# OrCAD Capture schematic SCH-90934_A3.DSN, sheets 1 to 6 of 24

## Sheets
1 C-21 BOOT MODE: size A4; title: IMX91LP4QSB-09; rev: A3; company: NXP Semiconductor; note: SCH-90934  PDF: SPF-90934; note: NO. 192 Liangjing Rd. Pudong New Area, ShangHai
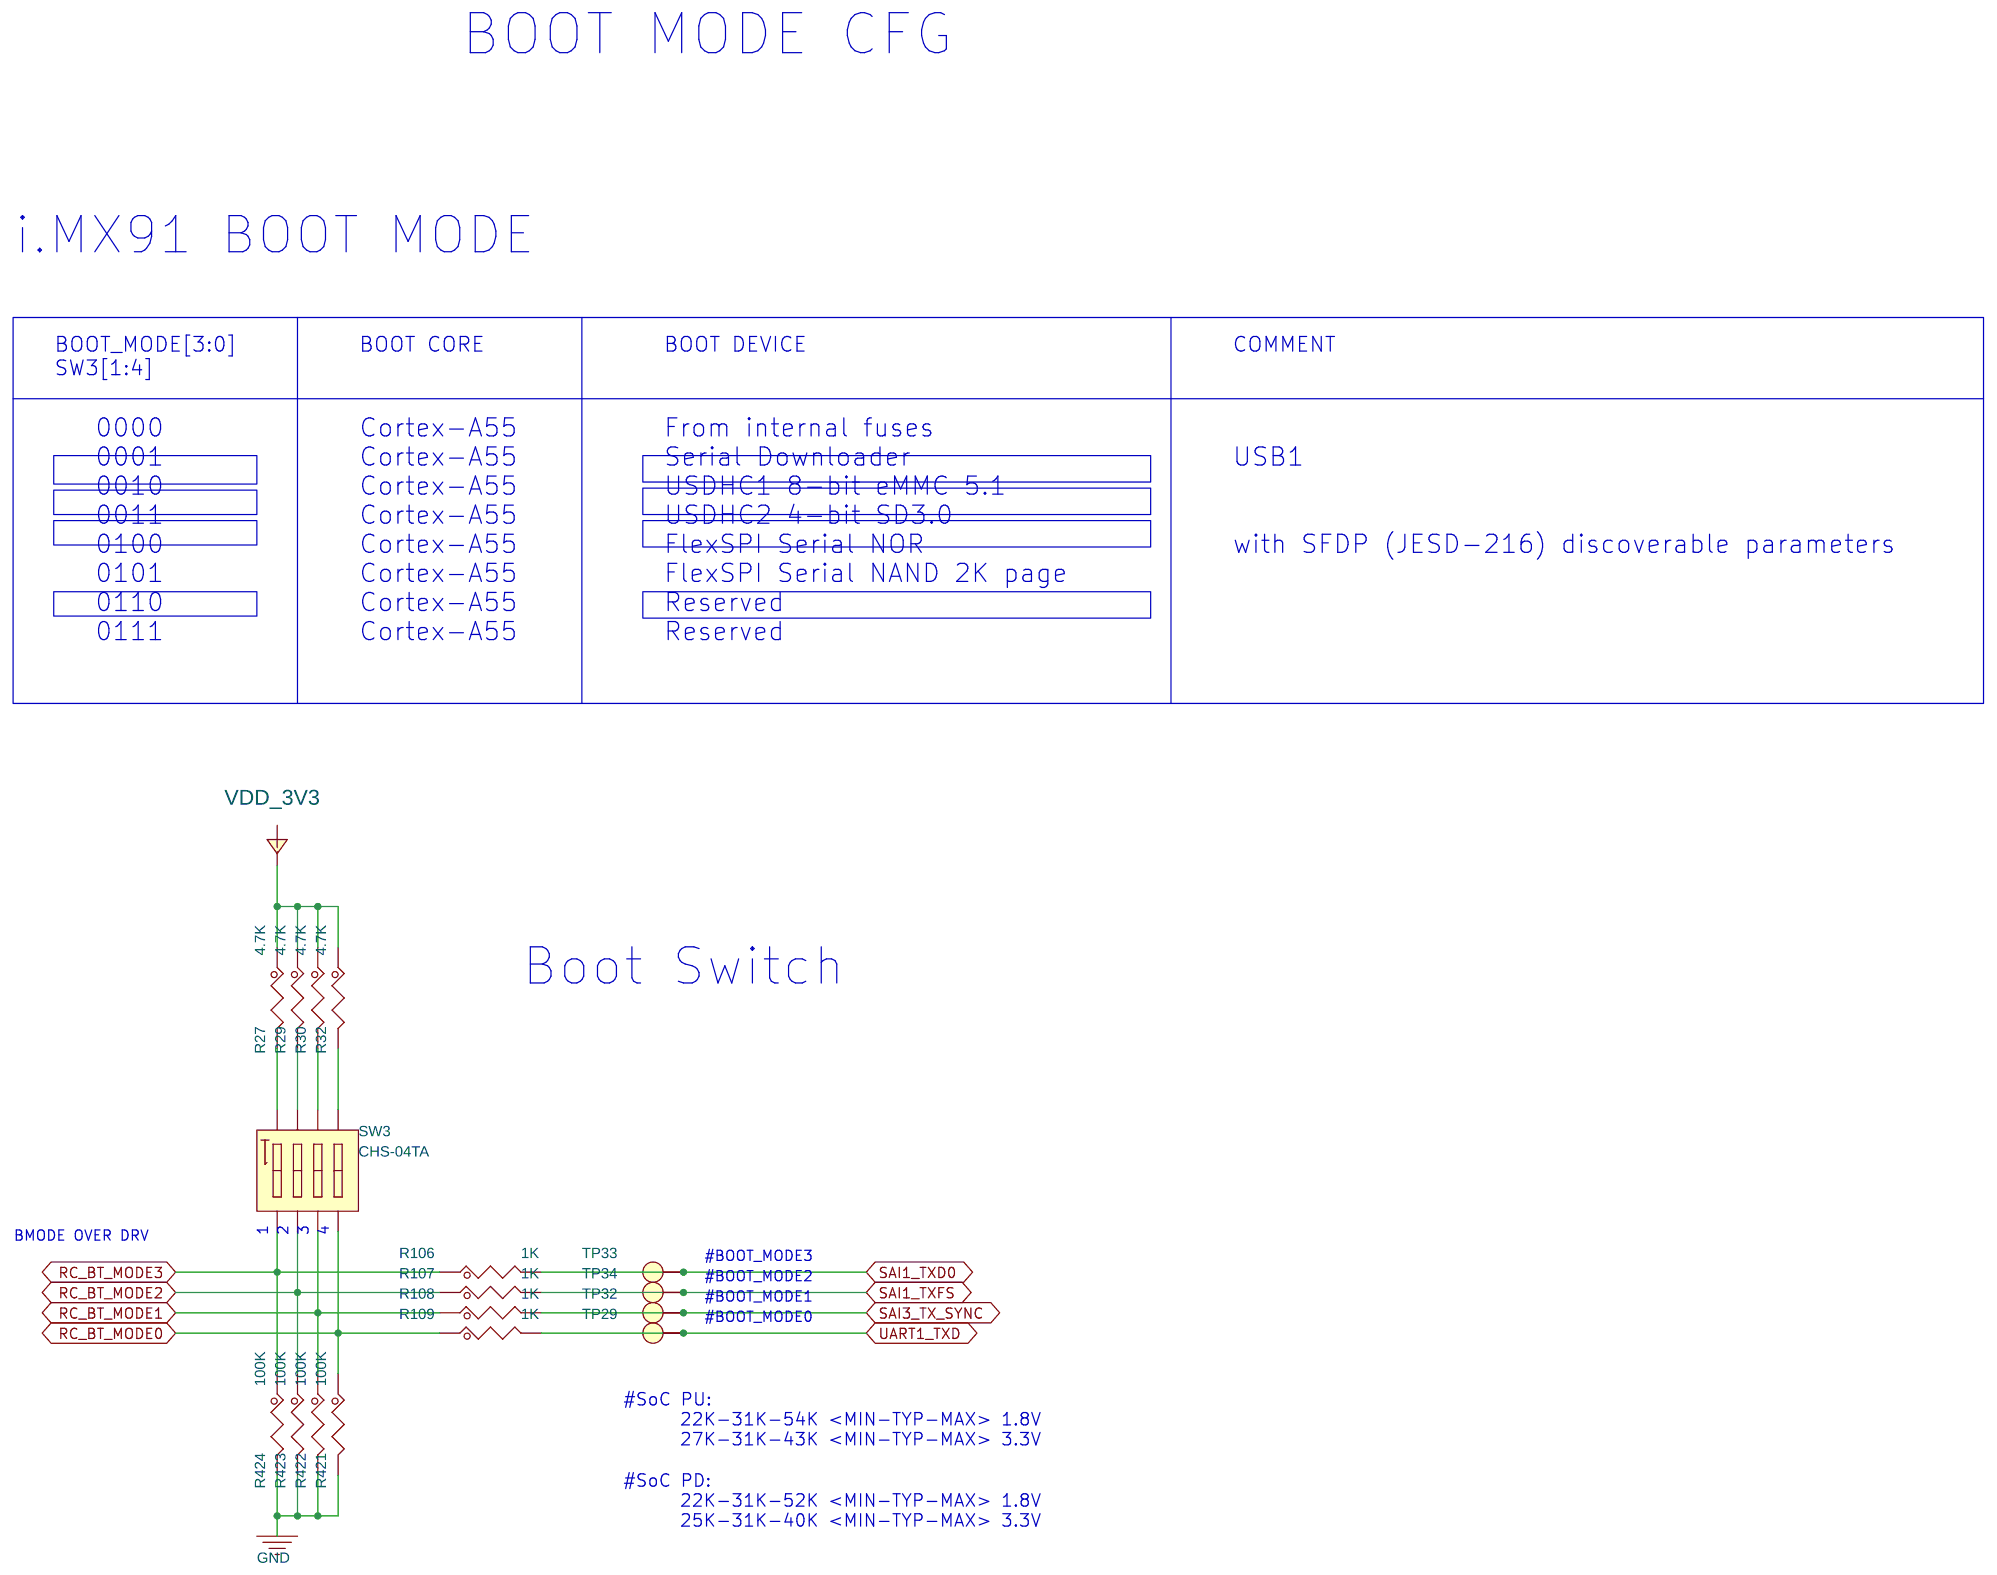
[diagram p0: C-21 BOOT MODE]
2 C-11 PWR MEAS: size A2; title: MCIMX91-SOM
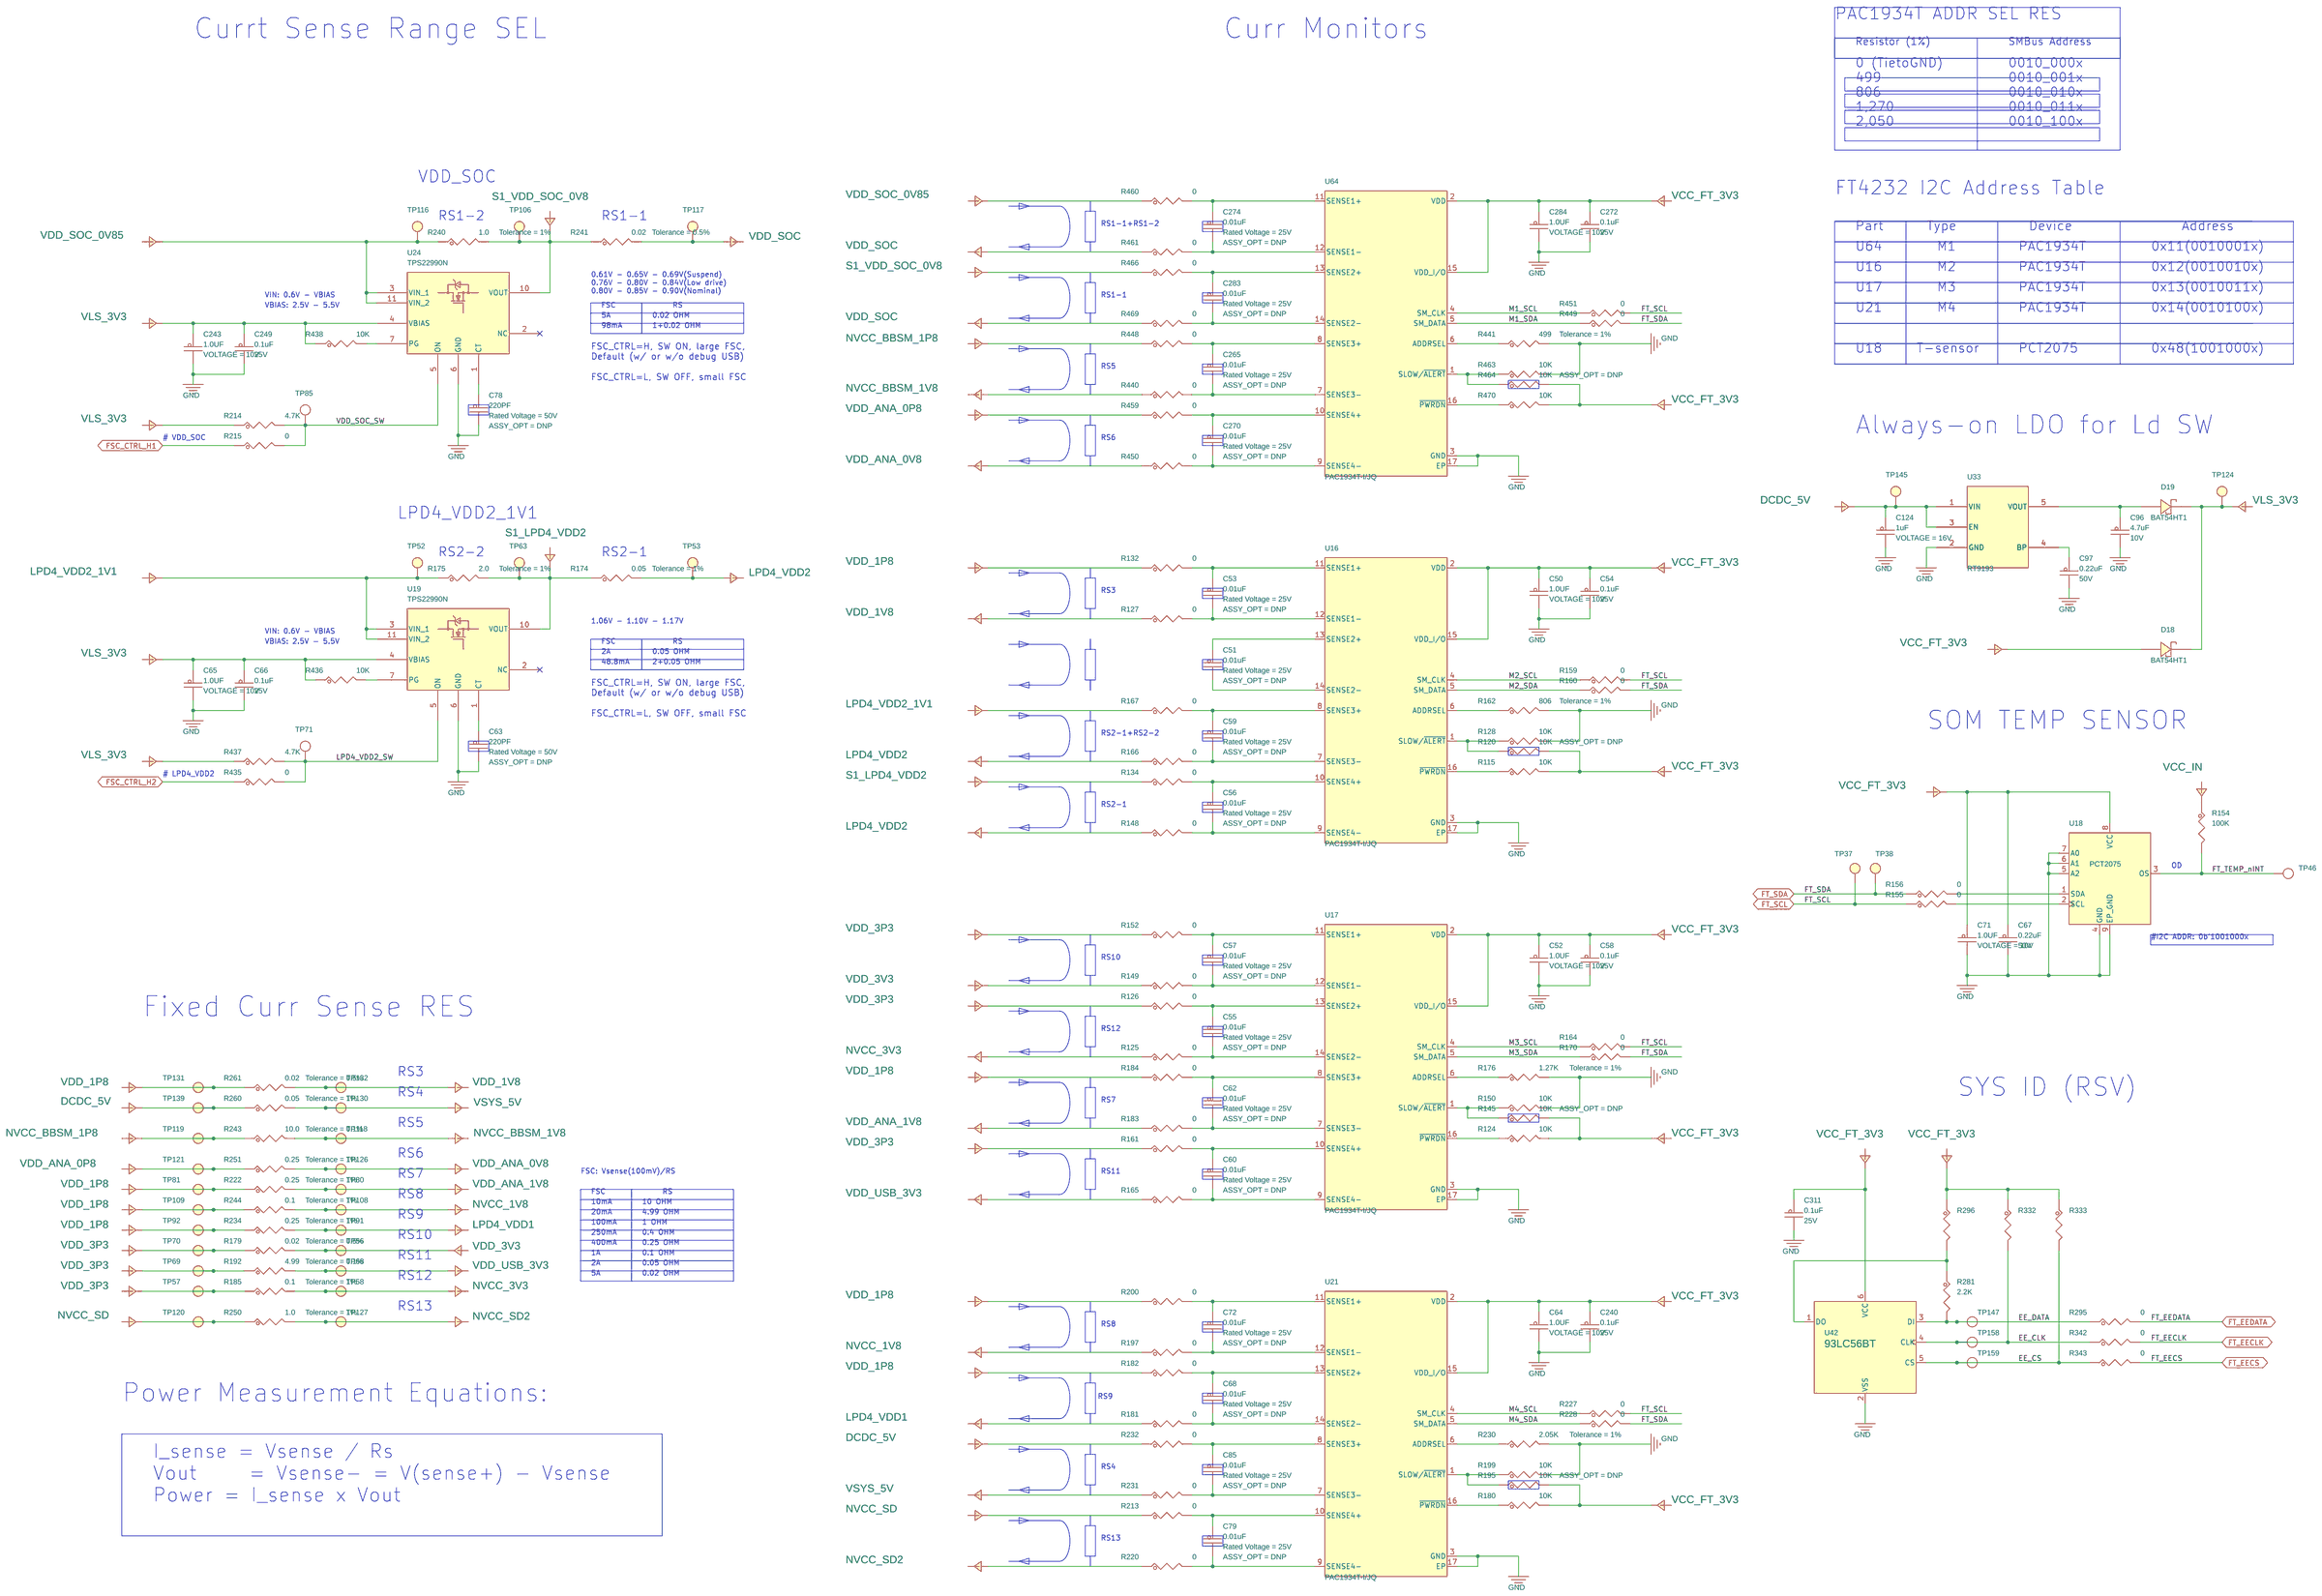
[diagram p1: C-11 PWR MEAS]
3 C-07 CPU MISC: size A3
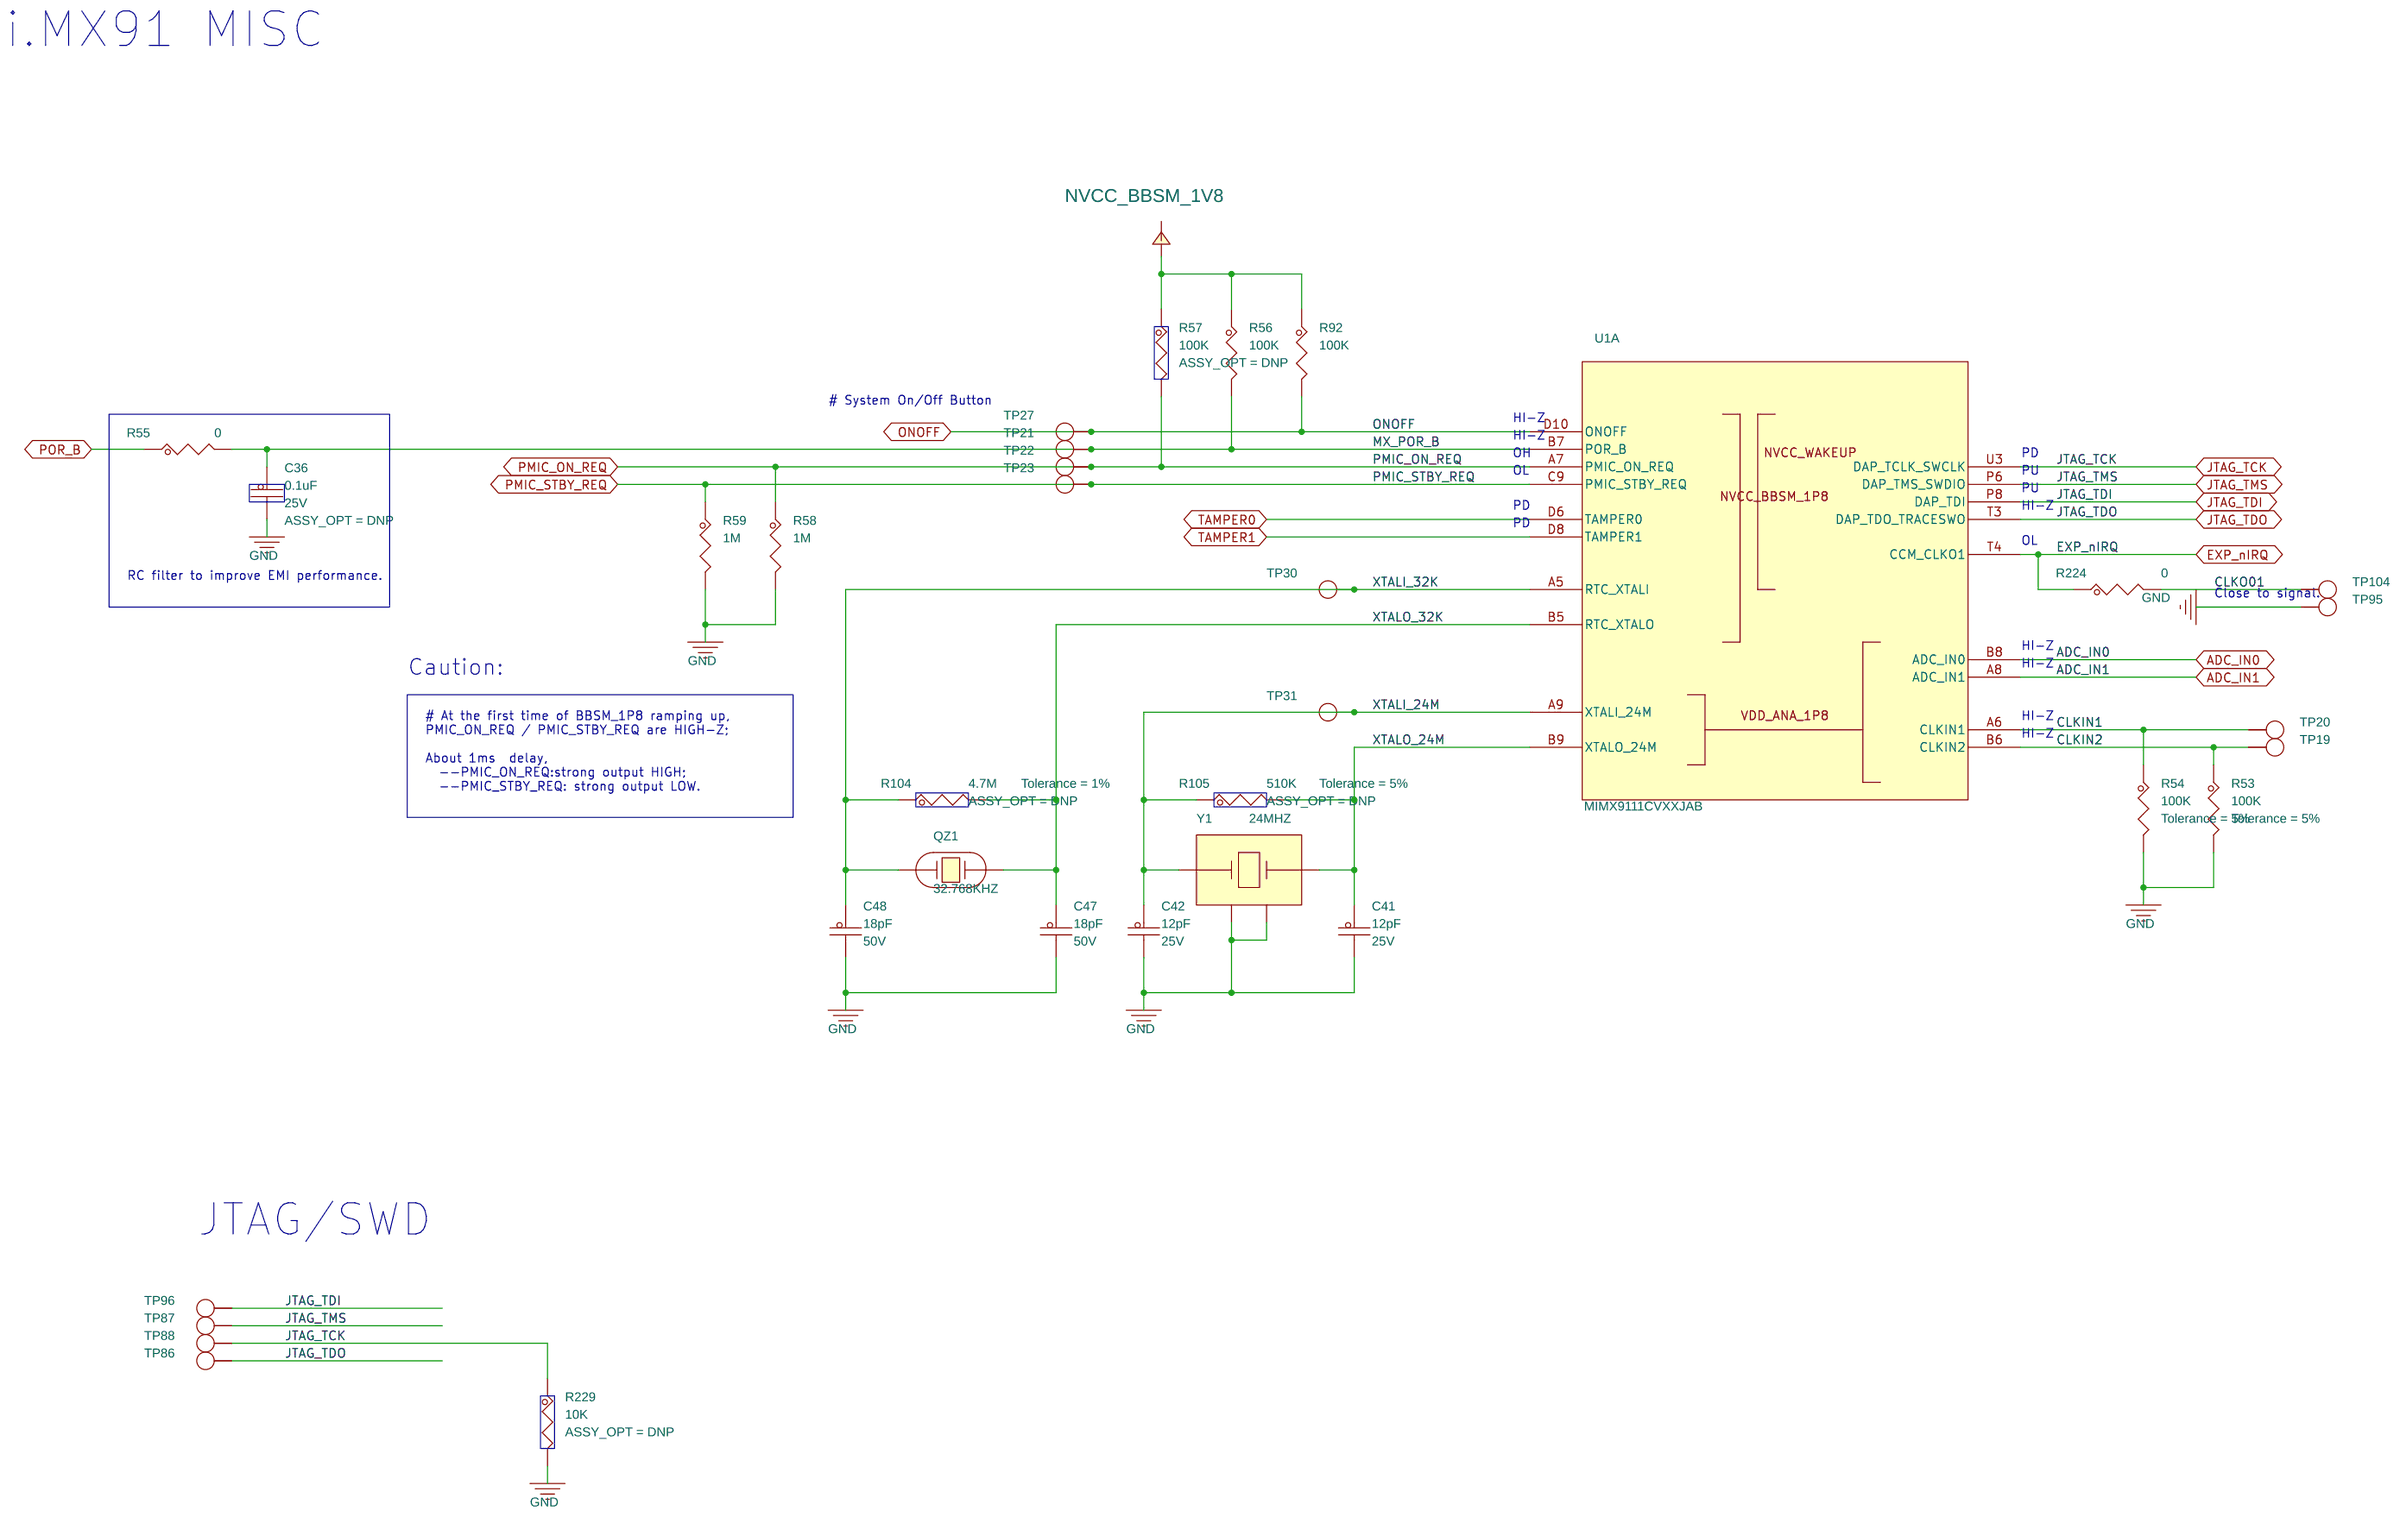
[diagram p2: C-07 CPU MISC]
4 X-24 IOMUX
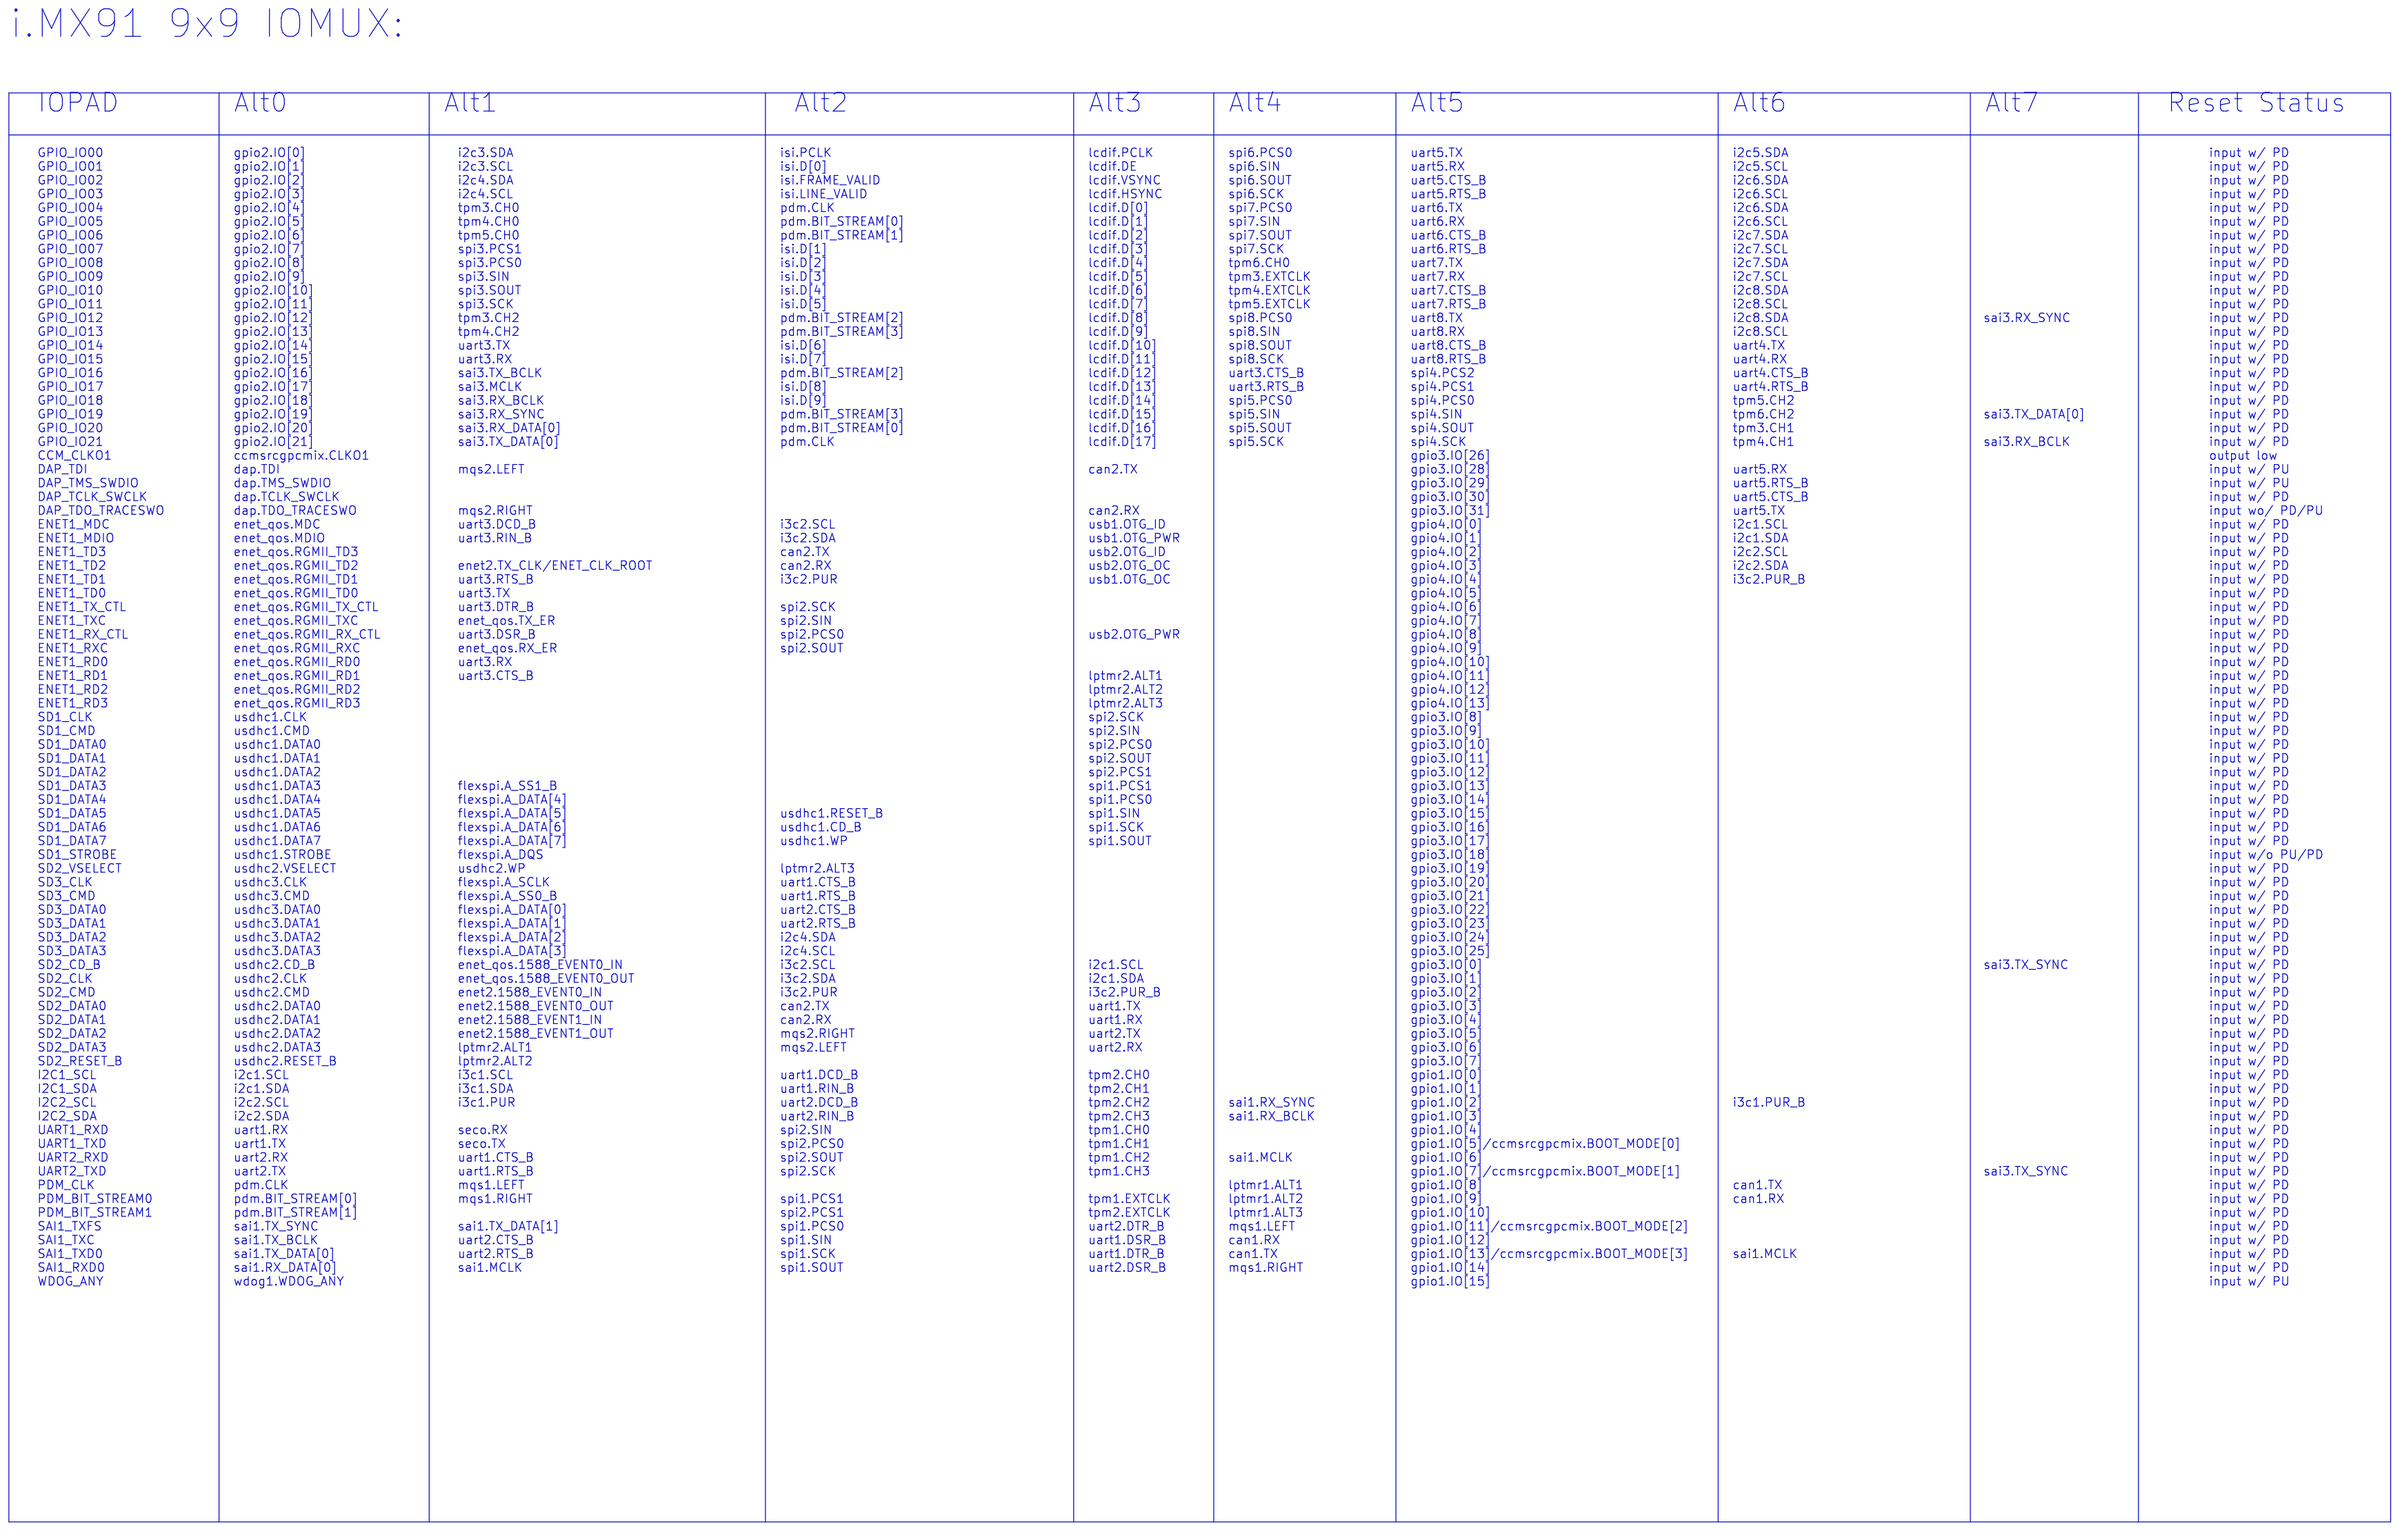
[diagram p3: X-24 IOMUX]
5 X-23 I2C TABLE
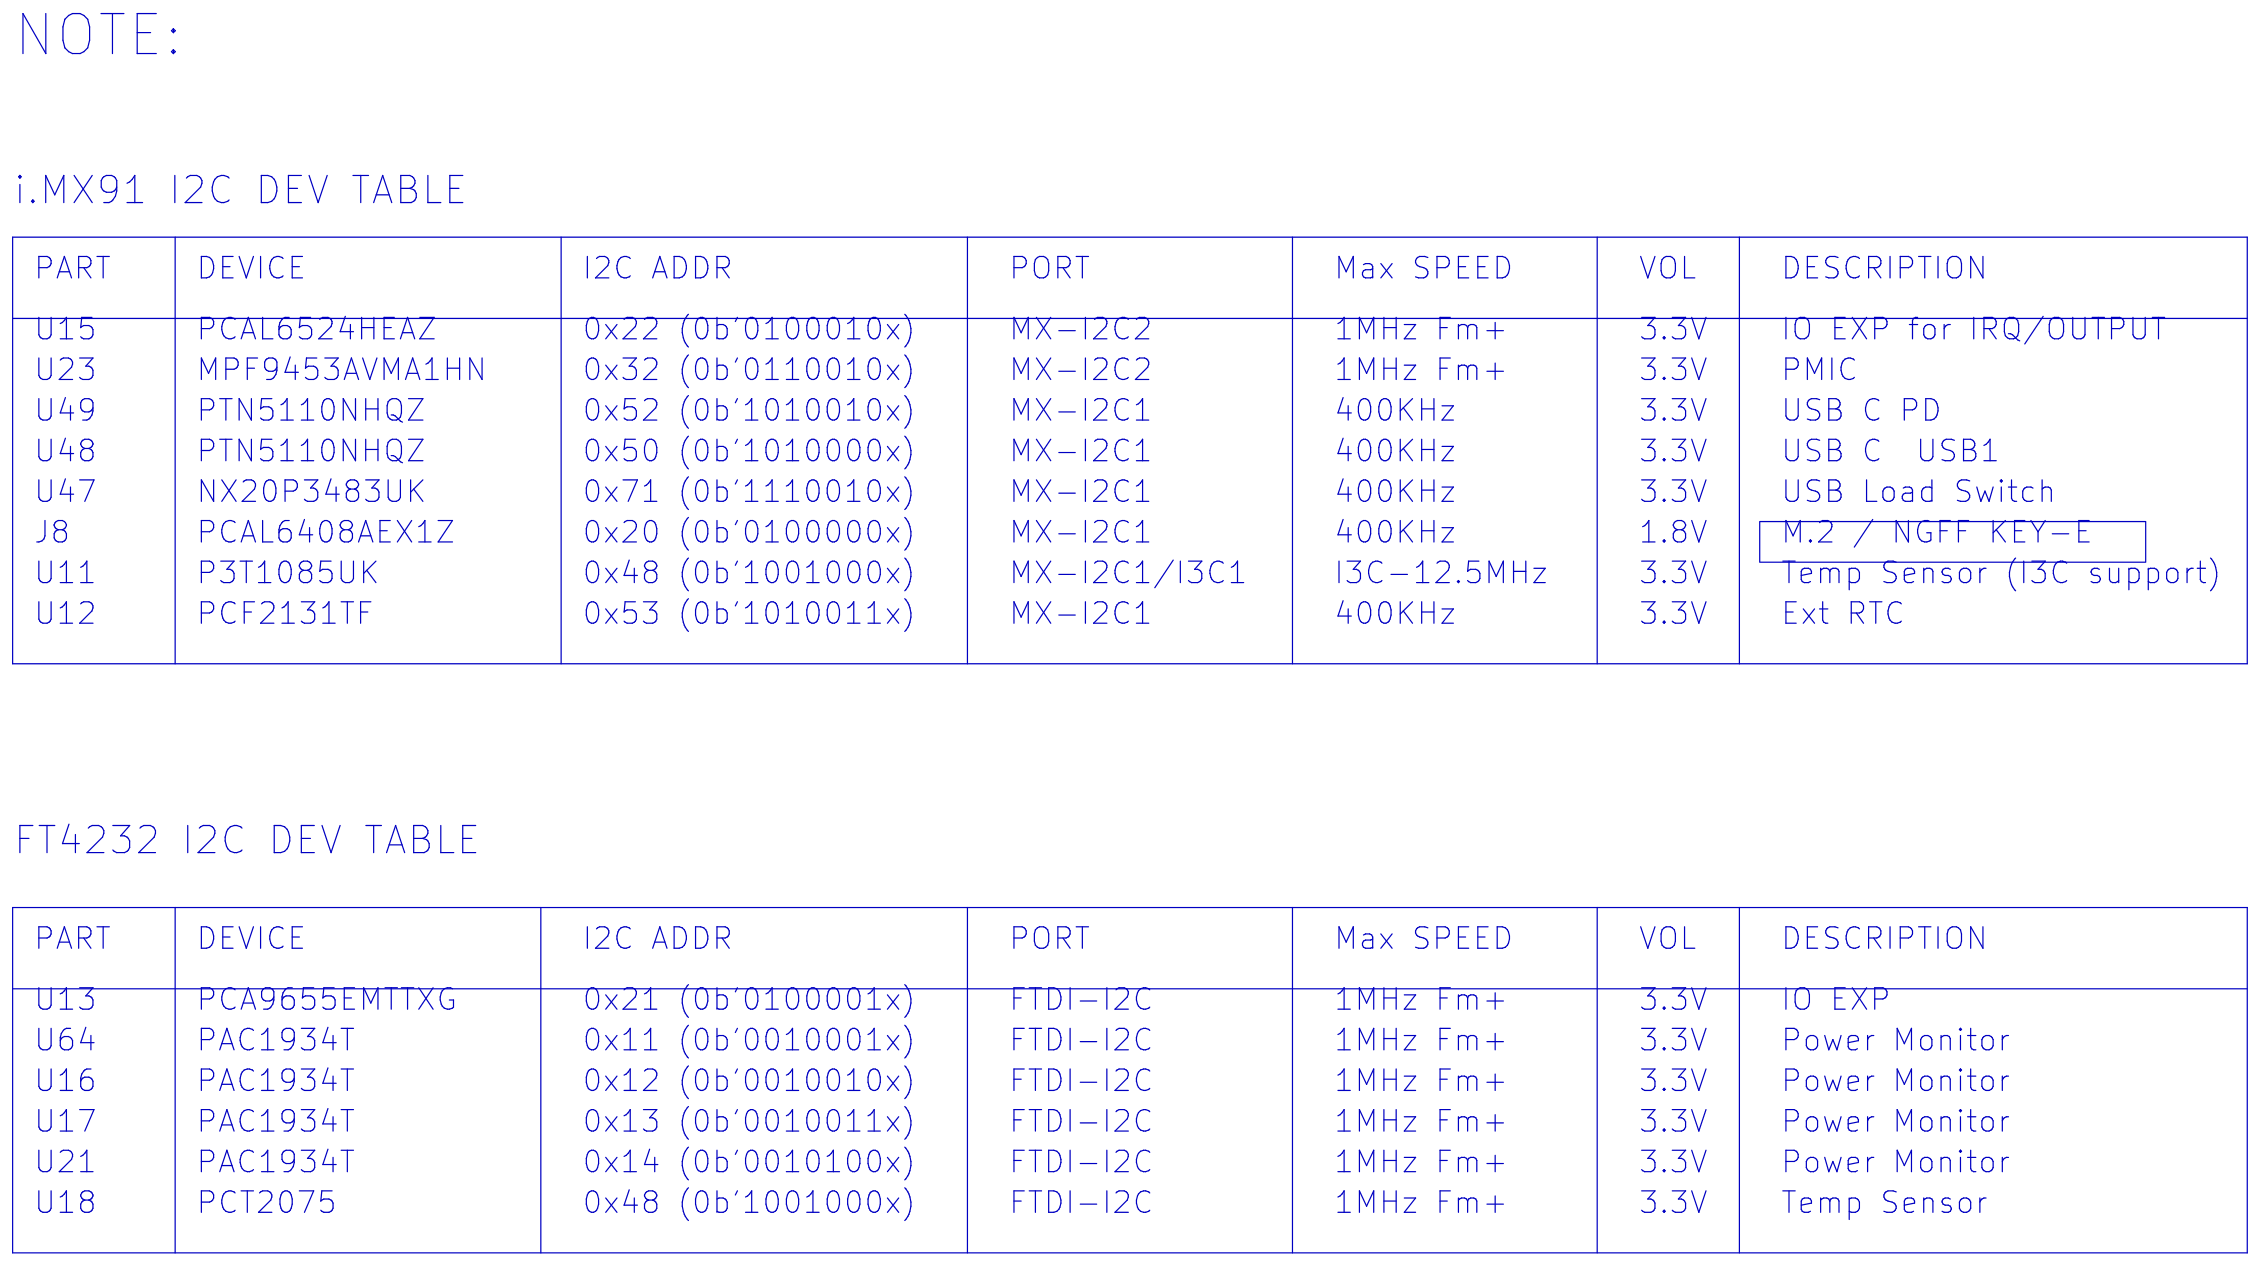
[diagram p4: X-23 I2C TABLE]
6 X-22 PWR MEAS Diagram
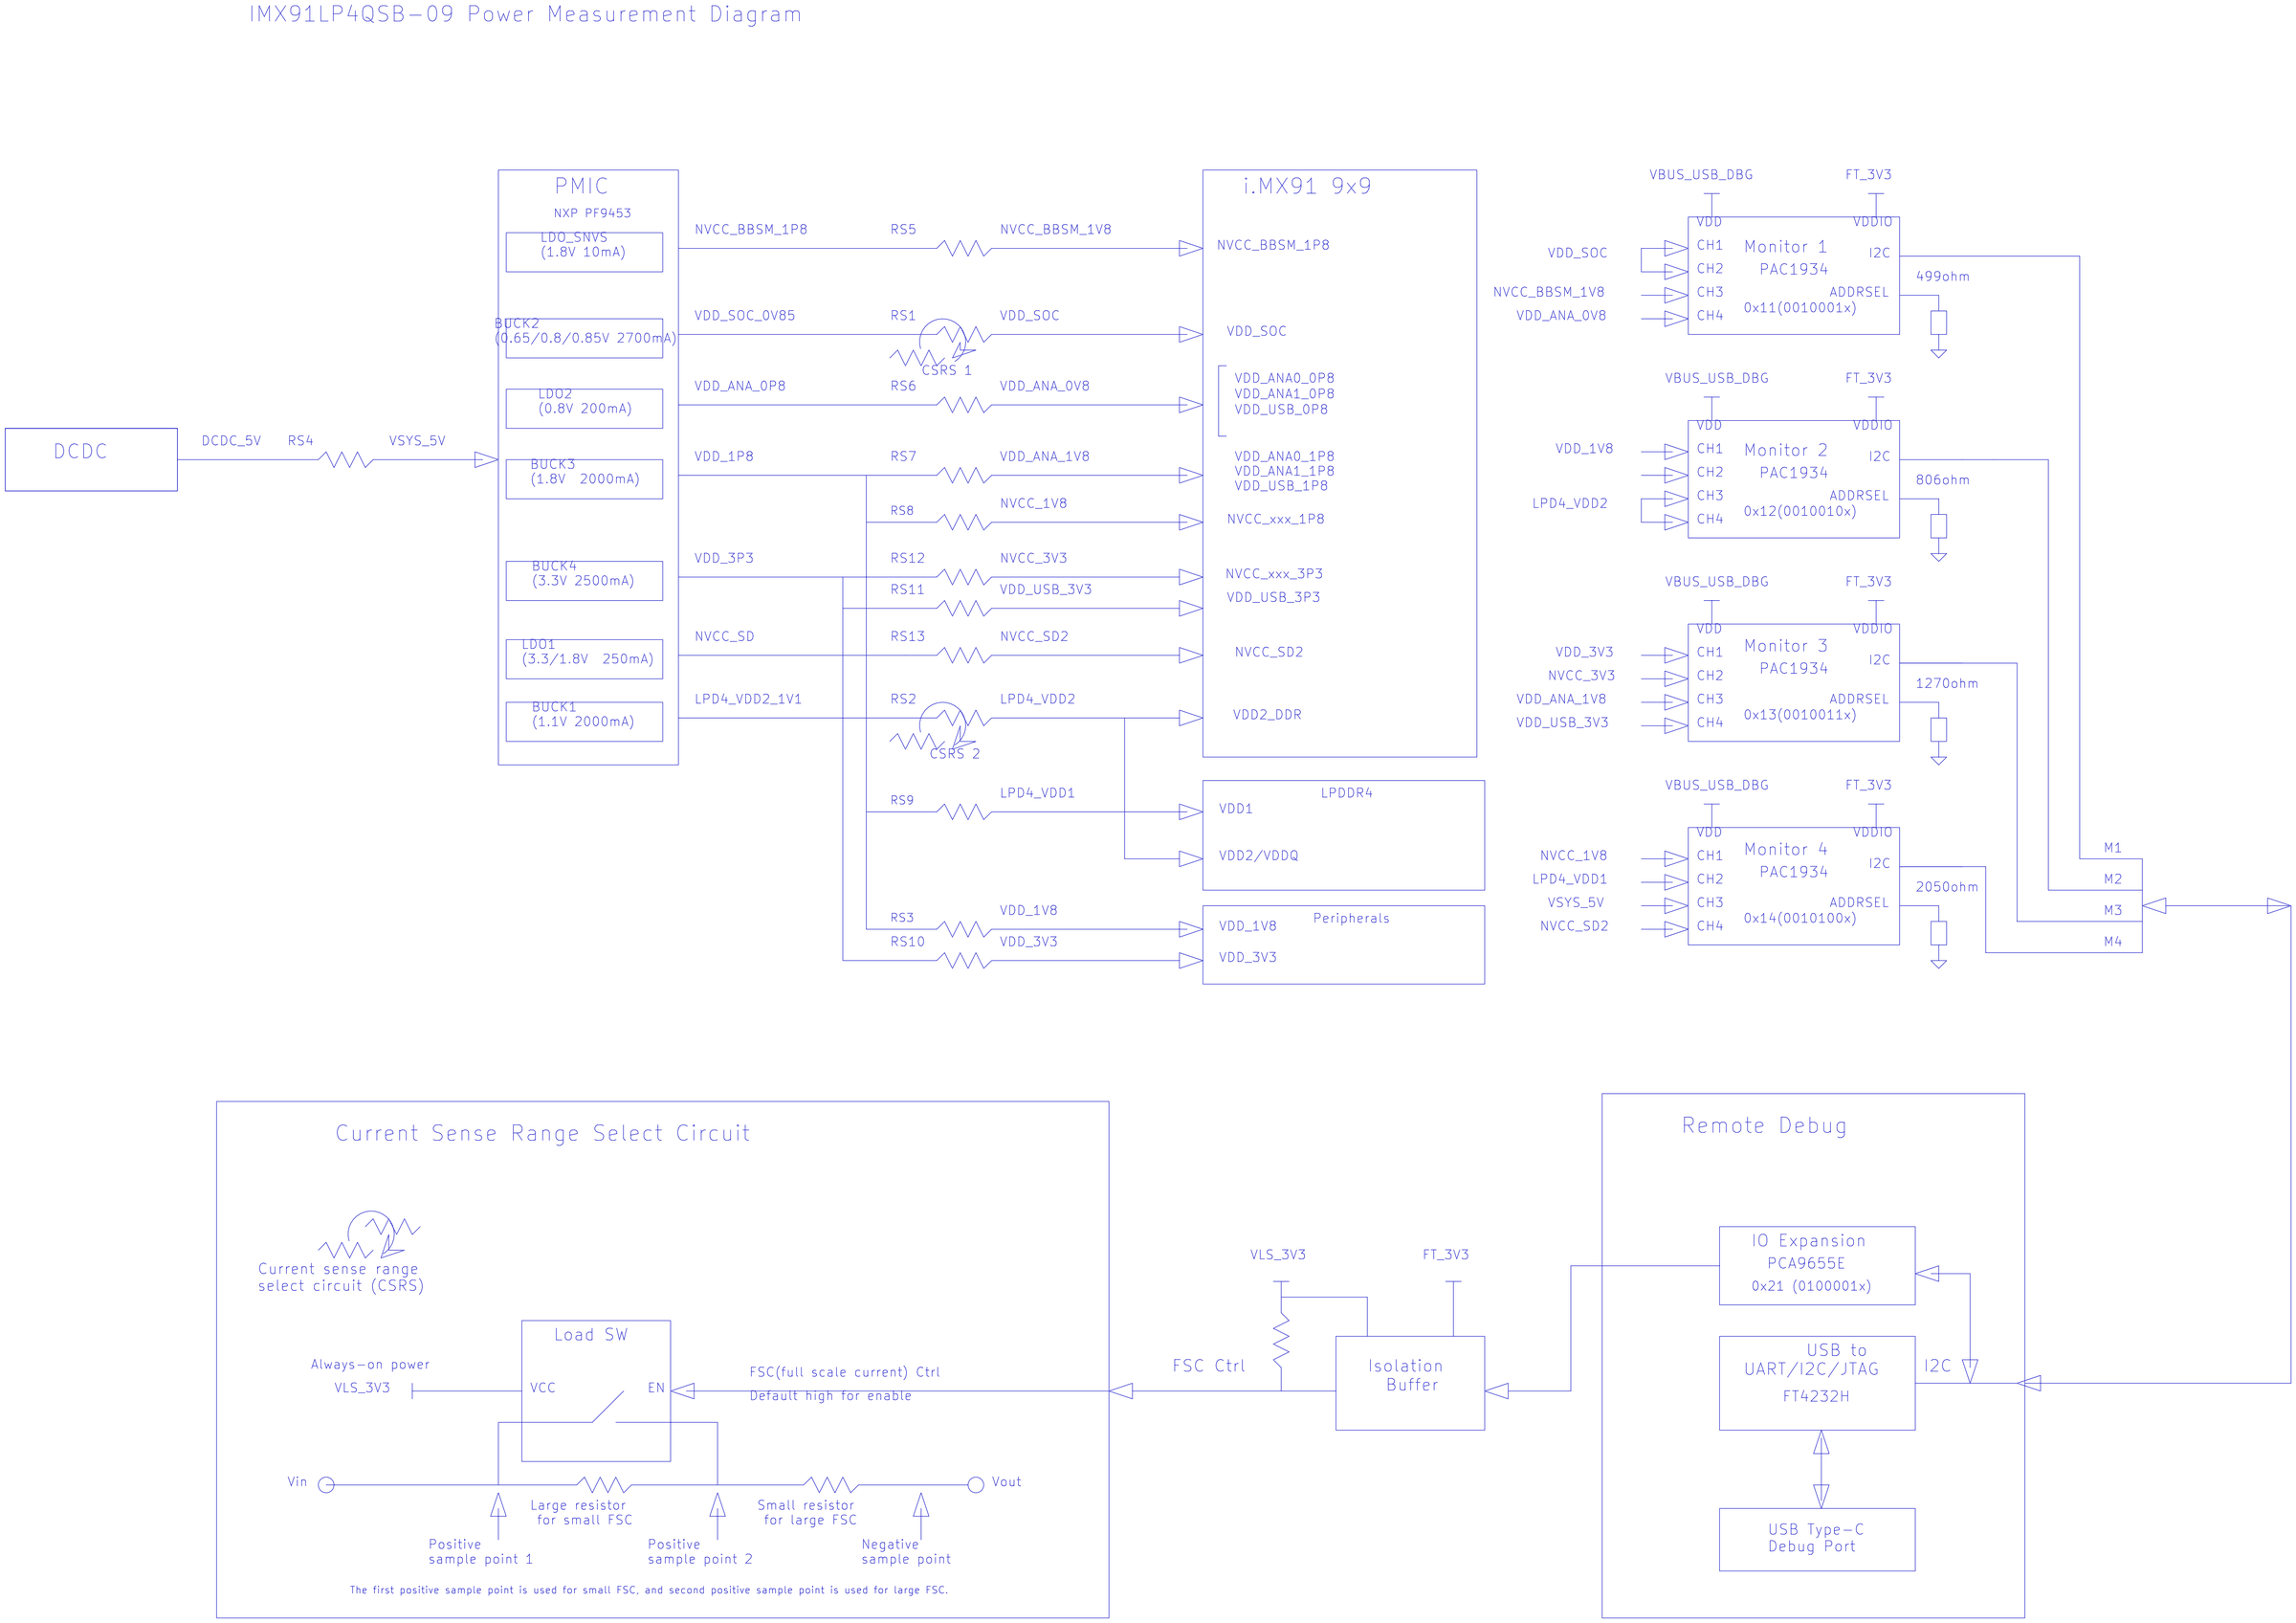
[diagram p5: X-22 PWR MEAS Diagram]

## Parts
sheet C-07 CPU MISC
C36  0.1uF  [CC0402_25]
C41  12pF  [0201_CC]
C42  12pF  [0201_CC]
C47  18pF  [0201_CC]
C48  18pF  [0201_CC]
QZ1  32.768KHZ  [XTAL2-3P2X1P5-SM]
R53  100K  [0402_CC]
R54  100K  [0402_CC]
R55  0  [0201_CC]
R56  100K  [0402_CC]
R57  100K  [0402_CC]
R58  1M  [0201_CC]
R59  1M  [0201_CC]
R92  100K  [0402_CC]
R104  4.7M  [RC0402_25]
R105  510K  [0402_CC]
R224  0  [0402_CC]
R229  10K  [0402_CC]
TP19  TPAD_020  [tpad_020]
TP20  TPAD_020  [tpad_020]
TP21  TPAD_020  [tpad_020]
TP22  TPAD_020  [tpad_020]
TP23  TPAD_020  [tpad_020]
TP27  TPAD_020  [tpad_020]
TP30  TPAD_015  [TPAD_015]
TP31  TPAD_015  [TPAD_015]
TP86  TPAD_020  [tpad_020]
TP87  TPAD_020  [tpad_020]
TP88  TPAD_020  [tpad_020]
TP95  TPAD_020  [tpad_020]
TP96  TPAD_020  [tpad_020]
TP104  TPAD_020  [tpad_020]
U1  MIMX9111CVXXJAB  [pbga208_0p5_9x9mm_sm]  (sections A,B,C,D,E,F)
Y1  24MHZ  [xtlosc4_3p2x2p5mm_sm]
sheet C-11 PWR MEAS
C50  1.0UF  [CC0402_25]
C51  0.01uF  [CC0402_25]
C52  1.0UF  [CC0402_25]
C53  0.01uF  [CC0402_25]
C54  0.1uF  [CC0402_25]
C55  0.01uF  [CC0402_25]
C56  0.01uF  [CC0402_25]
C57  0.01uF  [CC0402_25]
C58  0.1uF  [CC0402_25]
C59  0.01uF  [CC0402_25]
C60  0.01uF  [CC0402_25]
C62  0.01uF  [CC0402_25]
C63  220PF  [CC0402_25]
C64  1.0UF  [CC0402_25]
C65  1.0UF  [CC0402_25]
C66  0.1uF  [CC0402_25]
C67  0.22uF  [CC0402_25]
C68  0.01uF  [CC0402_25]
C71  1.0UF  [CC0402_25]
C72  0.01uF  [CC0402_25]
C78  220PF  [CC0402_25]
C79  0.01uF  [CC0402_25]
C85  0.01uF  [CC0402_25]
C96  4.7uF  [cc0402_tol0p15]
C97  0.22uF  [CC0402_25]
C124  1uF  [CC0402_25]
C240  0.1uF  [CC0402_25]
C243  1.0UF  [CC0402_25]
C249  0.1uF  [CC0402_25]
C265  0.01uF  [CC0402_25]
C270  0.01uF  [CC0402_25]
C272  0.1uF  [CC0402_25]
C274  0.01uF  [CC0402_25]
C283  0.01uF  [CC0402_25]
C284  1.0UF  [CC0402_25]
C311  0.1uF  [CC0402_25]
D18  BAT54HT1  [SOD323]
D19  BAT54HT1  [SOD323]
R115  10K  [0402_CC]
R120  10K  [0402_CC]
R124  10K  [0402_CC]
R125  0  [0402_CC]
R126  0  [0402_CC]
R127  0  [0402_CC]
R128  10K  [0402_CC]
R132  0  [0402_CC]
R134  0  [0402_CC]
R145  10K  [0402_CC]
R148  0  [0402_CC]
R149  0  [0402_CC]
R150  10K  [0402_CC]
R152  0  [0402_CC]
R154  100K  [0402_CC]
R155  0  [0402_CC]
R156  0  [0402_CC]
R159  0  [0201_CC]
R160  0  [0201_CC]
R161  0  [0402_CC]
R162  806  [RC0402_25]
R164  0  [0201_CC]
R165  0  [0402_CC]
R166  0  [0402_CC]
R167  0  [0402_CC]
R170  0  [0201_CC]
R174  0.05  [RC0805_OV]
R175  2.0  [RC0603_OV]
R176  1.27K  [RC0402_25]
R179  0.02  [RC0805_OV]
R180  10K  [0402_CC]
R181  0  [0402_CC]
R182  0  [0402_CC]
R183  0  [0402_CC]
R184  0  [0402_CC]
R185  0.1  [RC0805_OV]
R192  4.99  [RC0603_OV]
R195  10K  [0402_CC]
R197  0  [0402_CC]
R199  10K  [0402_CC]
R200  0  [0402_CC]
R213  0  [0402_CC]
R214  4.7K  [0402_CC]
R215  0  [0402_CC]
R220  0  [0402_CC]
R222  0.25  [RC0805_OV]
R227  0  [0201_CC]
R228  0  [0201_CC]
R230  2.05K  [RC0402_25]
R231  0  [0402_CC]
R232  0  [0402_CC]
R234  0.25  [RC0805_OV]
R240  1.0  [RC0603_OV]
R241  0.02  [RC0805_OV]
R243  10.0  [RC0603_OV]
R244  0.1  [RC0805_OV]
R250  1.0  [RC0603_OV]
R251  0.25  [RC0805_OV]
R260  0.05  [RC0805_OV]
R261  0.02  [RC0805_OV]
R281  2.2K  [RC0402_25]
R295  0  [0402_CC]
R296  10K  [0402_CC]
R332  10K  [0402_CC]
R333  10K  [0402_CC]
R342  0  [0402_CC]
R343  0  [0402_CC]
R435  0  [0402_CC]
R436  10K  [0402_CC]
R437  4.7K  [0402_CC]
R438  10K  [0402_CC]
R440  0  [0402_CC]
R441  499  [RC0402_25]
R448  0  [0402_CC]
R449  0  [0201_CC]
R450  0  [0402_CC]
R451  0  [0201_CC]
R459  0  [0402_CC]
R460  0  [0402_CC]
R461  0  [0402_CC]
R463  10K  [0402_CC]
R464  10K  [0402_CC]
R466  0  [0402_CC]
R469  0  [0402_CC]
R470  10K  [0402_CC]
TP37  TP_35MIL  [testpoint_35mil]
TP38  TP_35MIL  [testpoint_35mil]
TP46  TPAD_020  [tpad_020]
TP52  TP_35MIL  [testpoint_35mil]
TP53  TP_35MIL  [testpoint_35mil]
TP56  TP_35MIL  [testpoint_35mil]
TP57  TP_35MIL  [testpoint_35mil]
TP58  TP_35MIL  [testpoint_35mil]
TP63  TP_35MIL  [testpoint_35mil]
TP68  TP_35MIL  [testpoint_35mil]
TP69  TP_35MIL  [testpoint_35mil]
TP70  TP_35MIL  [testpoint_35mil]
TP71  TPAD_020  [tpad_020]
TP80  TP_35MIL  [testpoint_35mil]
TP81  TP_35MIL  [testpoint_35mil]
TP85  TPAD_020  [tpad_020]
TP91  TP_35MIL  [testpoint_35mil]
TP92  TP_35MIL  [testpoint_35mil]
TP106  TP_35MIL  [testpoint_35mil]
TP108  TP_35MIL  [testpoint_35mil]
TP109  TP_35MIL  [testpoint_35mil]
TP116  TP_35MIL  [testpoint_35mil]
TP117  TP_35MIL  [testpoint_35mil]
TP118  TP_35MIL  [testpoint_35mil]
TP119  TP_35MIL  [testpoint_35mil]
TP120  TP_35MIL  [testpoint_35mil]
TP121  TP_35MIL  [testpoint_35mil]
TP124  TP_35MIL  [testpoint_35mil]
TP126  TP_35MIL  [testpoint_35mil]
TP127  TP_35MIL  [testpoint_35mil]
TP130  TP_35MIL  [testpoint_35mil]
TP131  TP_35MIL  [testpoint_35mil]
TP132  TP_35MIL  [testpoint_35mil]
TP139  TP_35MIL  [testpoint_35mil]
TP145  TP_35MIL  [testpoint_35mil]
TP147  TPAD_020  [tpad_020]
TP158  TPAD_020  [tpad_020]
TP159  TPAD_020  [tpad_020]
U16  PAC1934T-I/JQ  [qfn16_0p65_4X4_a]
U17  PAC1934T-I/JQ  [qfn16_0p65_4X4_a]
U18  PCT2075  [hwson8_0p5_3p1x2p1]
U19  TPS22990N  [wson10_0p5_2p1x3p1]
U21  PAC1934T-I/JQ  [qfn16_0p65_4X4_a]
U24  TPS22990N  [wson10_0p5_2p1x3p1]
U33  RT9193  [sot23-5]
U42  93LC56BT  [sot23-6]
U64  PAC1934T-I/JQ  [qfn16_0p65_4X4_a]
sheet C-21 BOOT MODE
R27  4.7K  [RC0402_25]
R29  4.7K  [RC0402_25]
R30  4.7K  [RC0402_25]
R32  4.7K  [RC0402_25]
R106  1K  [0402_CC]
R107  1K  [0402_CC]
R108  1K  [0402_CC]
R109  1K  [0402_CC]
R421  100K  [0402_CC]
R422  100K  [0402_CC]
R423  100K  [0402_CC]
R424  100K  [0402_CC]
SW3  CHS-04TA  [sw_chs_04_a]
TP29  TP_35MIL  [testpoint_35mil]
TP32  TP_35MIL  [testpoint_35mil]
TP33  TP_35MIL  [testpoint_35mil]
TP34  TP_35MIL  [testpoint_35mil]

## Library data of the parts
C36 = CAP_NP: CAP CER 0.1UF 25V 10% X5R 0402; AGILE_PN: 150-78633; ASSY_OPT: DNP; CAD_APPROVED: Yes; FPLIST: CC0402_25,CC0402_HD,0402_CC; HEIGHT: 0.55MM; MFG_NAME01: YAGEO AMERICA; MFG_PN01: CC0402KRX5R8BB104; Package Size: 0402; ROHS: Yes; Rated Voltage: 25V; Temp Range: -55C to +85C; Tolerance: 10%; VOLTAGE: 25V
C41 C42 = CAP_NP: CAP CER 12PF 25V 5% C0G AEC-Q200 0201; AGILE_PN: 150-79813; CAD_APPROVED: Yes; FPLIST: CC0201,CC0201_HD,0201_CC; HEIGHT: 0.33MM; MFG_NAME01: TDK; MFG_PN01: CGA1A2C0G1E120J030BA; ROHS: Yes; Rated Voltage: 25V; Temp Range: -55C to +125C; Tolerance: 5%; VOLTAGE: 25V
C47 C48 = CAP_NP: CAP CER 18pF 50V 5% C0G 0201; AGILE_PN: 150-79476; CAD_APPROVED: Yes; FPLIST: CC0201,CC0201_HD,0201_CC; HEIGHT: 0.33MM; MFG_NAME01: MURATA; MFG_PN01: GRM0335C1H180JA01D; Package Size: 0201; Package Type: &#966;180mm Paper taping; ROHS: Yes; Rated Voltage: 50V; Temp Range: -55C to +125C; Tolerance: 5%; VOLTAGE: 50V
QZ1 = XTAL: XTAL 32.768KHZ 12.5PF 20PPM 3.2X1.5MM SMT; 3D_Mechanical_Footprint_File: http://fcl.am.freescale.net/ALLEGRO/step/xtal2-3p2x1p5-sm.step; AGILE_PN: 230-77653; CAD_APPROVED: Yes; HEIGHT: 0.9; MFG_NAME01: ABRACON CORPORATION; MFG_PN01: ABS07-32.768KHZ-T; ROHS: Yes
R53 R54 R56 R92 R154 R421-R424 = RES: RES MF 100K 1/16W 5% 0402; AGILE_PN: 470-75597; CAD_APPROVED: Yes; FPLIST: RC0402_25,RC0402_HD,0402_CC; HEIGHT: 0.40 MM; MFG_NAME01: VENKEL COMPANY; MFG_PN01: CR0402-16W-104JT; ROHS: Yes; Temp Range: -55C to +155C; Tolerance: 5%; VOLTAGE: 50V
R55 R159 R160 R164 R170 R227 R228 R449 R451 = RES: RES MF ZERO OHM 1/20W -- 0201; AGILE_PN: 470-76631; CAD_APPROVED: Yes; FPLIST: RC0201,0201_CC,RC0201_X2; HEIGHT: 0.30 MM; MFG_NAME01: BOURNS; MFG_PN01: CR0201-J/-000GLF; ROHS: Yes
R57 = RES: RES MF 100K 1/16W 5% 0402; AGILE_PN: 470-75597; ASSY_OPT: DNP; CAD_APPROVED: Yes; FPLIST: RC0402_25,RC0402_HD,0402_CC; HEIGHT: 0.40 MM; MFG_NAME01: VENKEL COMPANY; MFG_PN01: CR0402-16W-104JT; ROHS: Yes; Temp Range: -55C to +155C; Tolerance: 5%; VOLTAGE: 50V
R58 R59 = RES: RES MF 1.0M 1/20W 5% AEC-Q200 0201; AGILE_PN: 470-79975; CAD_APPROVED: Yes; FPLIST: RC0201,0201_CC; HEIGHT: 0.26MM; MFG_NAME01: PANASONIC; MFG_PN01: ERJ-1GNJ105C; ROHS: Yes; Temp Range: 55°C ~ 125°C; Temp_Range: 55°C ~ 125°C; Tolerance: 5%; VOLTAGE: 25V
R104 = RES: RES MF 4.7M  1/16W 1% 0402; AGILE_PN: 470-31250; ASSY_OPT: DNP; CAD_APPROVED: Yes; FPLIST: RC0402_25,RC0402_HD,0402_CC; HEIGHT: 0.40 MM; MFG_NAME01: YAGEO AMERICA; MFG_PN01: RC0402FR-074M7L; ROHS: Yes; Temp Range: -55°C ~ 155°C; Tolerance: 1%; VOLTAGE: 50V
R105 = RES: RES MF 510K 1/16W 5% 0402; AGILE_PN: 470-76166; ASSY_OPT: DNP; CAD_APPROVED: Yes; FPLIST: RC0402_25,RC0402_HD,0402_CC; HEIGHT: 0.4 MM; MFG_NAME01: PANASONIC; MFG_PN01: ERJ-2GEJ514X; ROHS: Yes; Tolerance: 5%
R125-R127 R132 R134 R148 R149 R152 R155 R156 R161 R165-R167 R181-R184 R197 R200 R213 R215 R220 R224 R231 R232 R295 R342 R343 R435 R440 R448 R450 R459-R461 R466 R469 = RES: RES MF ZERO OHM 1/16W 5% 0402; AGILE_PN: 470-75394; CAD_APPROVED: Yes; FPLIST: RC0402_25,RC0402_HD,RC0402_X2,0402_CC; HEIGHT: 0.45; MFG_NAME01: YAGEO AMERICA; MFG_PN01: RC0402JR-070RL; ROHS: Yes; Temp Range: -55 to +155C; Tolerance: 5%; VOLTAGE: 1/16W
R120 R145 R195 R229 R464 = RES: RES MF 10K 1/16W 5% 0402; AGILE_PN: 470-75557; ASSY_OPT: DNP; CAD_APPROVED: Yes; FPLIST: RC0402_25,RC0402_HD,0402_CC; HEIGHT: 0.4 MM; MFG_NAME01: VISHAY INTERTECHNOLOGY; MFG_PN01: CRCW040210K0JNED; ROHS: Yes; Tolerance: 5%
TP19-TP23 TP27 TP46 TP71 TP85-TP88 TP95 TP96 TP104 TP147 TP158 TP159 = TESTLOOP: TEST POINT PAD 0.5MM DIA SMT, NO PART TO ORDER; AGILE_PN: 211-77484; ASSY_OPT: DNP; CAD_APPROVED: Yes; HEIGHT: 0.1MM; ROHS: Yes
TP30 TP31 = TESTLOOP: TEST POINT PAD 15MIL DIA SMT, NO PART TO ORDER; AGILE_PN: 211-76645; ASSY_OPT: DNP; CAD_APPROVED: Yes; HEIGHT: 0.1MM; MFG_NAME01: NOTACOMPONENT; MFG_PN01: NOTACOMPONENT; ROHS: Yes
U1 = MIMX9122DVXxLAA_BGA208_A: IC CPU SINGLE CORTEX A55 1.4GHz -- FCPBGA208; 3D_Mechanical_Footprint_File: http://fcl.am.freescale.net/ALLEGRO/step/pbga208_0p5_9x9mm_sm.STEP; AGILE_PN: 330-10031; CAD_APPROVED: Yes; HEIGHT: 1mm; MFG_NAME01: NXP SEMICONDUCTOR; Package Size: FCPBGA208; ROHS: NULL; Temp Range: -40  °C to +105 °C
Y1 = XTAL_13: XTAL 24MHZ 9pF -- SMT 3.2X2.5MM; AGILE_PN: 230-77392; CAD_APPROVED: Yes; HEIGHT: 0.60; MFG_NAME01: EPSON TOYOCOM CORPORATION; MFG_PN01: TSX-3225 24.0000MF15X-AC3; ROHS: Yes
C50 C52 C64 C65 C71 C243 C284 = CAP_NP: CAP CER 1.0UF 10V 10% X5R 0402; AGILE_PN: 150-75772; CAD_APPROVED: Yes; FPLIST: CC0402_25,CC0402_HD,0402_CC; HEIGHT: 0.6MM; MFG_NAME01: YAGEO AMERICA; MFG_PN01: CC0402KRX5R6BB105; Package Size: 0402; ROHS: Yes; Rated Voltage: 10V; SIGNAL_MODEL: DEFAULT_CAPACITOR_1e+06pF_2_1; TOL: 10%; Temp Range: -55C to +85C; Tolerance: 10%; VOLTAGE: 10V; voltage rating: 10V
C51 C53 C55-C57 C59 C60 C62 C68 C72 C79 C85 C265 C270 C274 C283 = CAP_NP: CAP CER 0.01uF 25V 5% X7R 0402; 3D_Mechanical_Footprint_File: http://fcl.am.freescale.net/ALLEGRO/step/cc0402_25.STEP; AGILE_PN: 150-81047; ASSY_OPT: DNP; CAD_APPROVED: Yes; FPLIST: CC0402_25,CC0402_HD,0402_CC,capc0402_l; HEIGHT: 0.55 MM; MFG_NAME01: KEMET; MFG_PN01: C0402C103J3RAC7867; Package Size: 0402 (1005 Metric); Package Type: Surface Mount, MLCC; ROHS: Yes; Rated Voltage: 25V; Temp Range: -55C to +125C; Tolerance: 5%
C54 C58 C66 C240 C249 C272 C311 = CAP_NP: CAP CER 0.1UF 25V 10% X5R 0402; AGILE_PN: 150-78633; CAD_APPROVED: Yes; FPLIST: CC0402_25,CC0402_HD,0402_CC; HEIGHT: 0.55MM; MFG_NAME01: YAGEO AMERICA; MFG_PN01: CC0402KRX5R8BB104; Package Size: 0402; ROHS: Yes; Rated Voltage: 25V; Temp Range: -55C to +85C; Tolerance: 10%; VOLTAGE: 25V
C63 C78 = CAP_NP: CAP CER 220PF 50V 5% C0G 0402; AGILE_PN: 150-30297; ASSY_OPT: DNP; CAD_APPROVED: Yes; FPLIST: CC0402_25,CC0402_HD,0402_CC,capc0402_l; HEIGHT: 0.55MM; MFG_NAME01: KEMET; MFG_PN01: C0402C221J5GAC; Package Size: 0402; ROHS: Yes; Rated Voltage: 50V; Temp Range: -55C to +125C; Tolerance: 5%
C67 C97 = CAP_NP: CAP CER 0.22uF 50V 10% X5R 0402; AGILE_PN: 150-79999; CAD_APPROVED: Yes; FPLIST: CC0402_25,CC0402_HD,0402_CC; HEIGHT: 0.55MM; MFG_NAME01: TAIYO YUDEN; MFG_PN01: UMK105BJ224KV-F; Package Size: 0402; ROHS: Yes; Rated Voltage: 50V; Temp Range: -55C to +85C; Temp_Range: -55°C to +85°C; Tolerance: 10%; VOLTAGE: 50V
C96 = CAP_NP: CAP CER 4.7uF 10V 10% X5R 0402; AGILE_PN: 150-80044; CAD_APPROVED: Yes; FPLIST: cc0402_tol0p15,cc0402_tol0p15_ov,0402_cc_nsp; HEIGHT: 0.65MM; MFG_NAME01: SAMSUNG ELECTRO MECHANICS; MFG_PN01: CL05A475KP5NRNC; ROHS: Yes; Rated Voltage: 10V; Temp Range: -55C to +85C; Tolerance: 10%; VOLTAGE: 10V
C124 = CAP_NP: CAP CER 1uF 16V 10% X5R 0402; AGILE_PN: 150-78973; CAD_APPROVED: Yes; FPLIST: CC0402_25,CC0402_HD,0402_CC; HEIGHT: 0.55 MM; MFG_NAME01: TDK; MFG_PN01: C1005X5R1C105K; ROHS: Yes; Rated Voltage: 16V; Temp Range: -55C to +85C; Tolerance: 10%; VOLTAGE: 16V; voltage rating: 16V
D18 D19 = DIODE_SCHTKY: DIODE SCH 30V 200MA -- SOD323; AGILE_PN: 480-30039; CAD_APPROVED: Yes; HEIGHT: 1.15; MFG_NAME01: ON SEMICONDUCTOR; MFG_PN01: BAT54HT1G
R115 R124 R128 R150 R180 R199 R296 R332 R333 R436 R438 R463 R470 = RES: RES MF 10K 1/16W 5% 0402; AGILE_PN: 470-75557; CAD_APPROVED: Yes; FPLIST: RC0402_25,RC0402_HD,0402_CC; HEIGHT: 0.4 MM; MFG_NAME01: VISHAY INTERTECHNOLOGY; MFG_PN01: CRCW040210K0JNED; ROHS: Yes; Tolerance: 5%
R162 = RES: RES TF 806 OHM 1% 1/10W AEC-Q200 0402; AGILE_PN: 470-81001; CAD_APPROVED: Yes; FPLIST: RC0402_25,RC0402_HD,0402_CC; HEIGHT: 0.4MM; MFG_NAME01: PANASONIC; MFG_PN01: ERJ-2RKF8060X; ROHS: Yes; Tolerance: 1%
R174 R260 = RES: RES MF 0.05OHM 1/4W 1% 0805; AGILE_PN: 470-79239; CAD_APPROVED: Yes; FPLIST: RC0805_OV,RC0805,0805_CC; HEIGHT: 0.46MM; MFG_NAME01: VISHAY INTERTECHNOLOGY; MFG_PN01: WSL0805R0500FEA18; ROHS: Yes; Tolerance: 1%
R175 = RES: RES MF 2.0 OHM 1/8W 1% AEC-Q200 0603; AGILE_PN: 470-81851; CAD_APPROVED: Yes; FPLIST: RC0603_OV,RC0603,0603_CC; HEIGHT: 0.55MM; MFG_NAME01: KOA SPEER; MFG_PN01: RK73H1JTTD2R00F; ROHS: Yes; Temp Range: -55°C to +155°C; Tolerance: 1%
R176 = RES: RES MF 1.27K  1/10W 1% AEC-Q200 0402; AGILE_PN: 470-30846; CAD_APPROVED: Yes; FPLIST: RC0402_25,RC0402_HD,0402_CC; HEIGHT: 0.40 MM; MFG_NAME01: KOA SPEER; MFG_PN01: RK73H1ETTP1271F; ROHS: Yes; Temp Range: -55°C to +155°C; Tolerance: 1%; VOLTAGE: 50V
R179 R241 R261 = RES: RES MF 0.02OHM 1/4W 0.5% 0805; AGILE_PN: 470-79241; CAD_APPROVED: Yes; FPLIST: RC0805_OV,RC0805,0805_CC; HEIGHT: 0.46MM; MFG_NAME01: VISHAY INTERTECHNOLOGY; MFG_PN01: WSL0805R0200DEA18; ROHS: Yes; Tolerance: 0.5%
R185 R244 = RES: RES MF 0.1 OHM 1/4W 1% AEC-Q200 0805; AGILE_PN: 470-82403; CAD_APPROVED: Yes; FPLIST: RC0805_OV,RC0805,0805_CC; HEIGHT: 0.584MM; MFG_NAME01: VISHAY INTERTECHNOLOGY; MFG_PN01: WSL0805R1000FEA18; ROHS: Yes; Temp Range: -65° C to +170° C; Tolerance: 1%
R192 = RES: RES MF 4.99 OHM 0.1% 1/16W 0603; AGILE_PN: 470-82515; CAD_APPROVED: Yes; FPLIST: RC0603_OV,RC0603,0603_CC; HEIGHT: 0.55MM; MFG_NAME01: TE CONNECTIVITY LTD; MFG_PN01: CPF0603B4R99E1; Package Size: 0603 (1608 Metric); ROHS: Yes; Temp Range: -55°C ~ 155°C; Tolerance: 0.1%
R214 R437 = RES: RES MF 4.7K 1/10W 5% AEC-Q200 0402; AGILE_PN: 470-82064; CAD_APPROVED: Yes; FPLIST: RC0402_25,RC0402_HD,0402_CC,RC0402_X2; HEIGHT: 0.41mm; MFG_NAME01: KOA SPEER; MFG_PN01: RK73B1ETTP472J; ROHS: Yes; Temp Range: -55C to +155C; Tolerance: 5%; VOLTAGE: 50V
R222 R234 R251 = RES: RES 0.25 OHM 1% 1/8W 0805; AGILE_PN: 470-82521; CAD_APPROVED: Yes; FPLIST: RC0805_OV,RC0805,0805_CC; HEIGHT: 0.6MM; MFG_NAME01: Yageo; MFG_PN01: RL0805FR-070R25L; Package Size: 0805 (2012 Metric); ROHS: Yes; Temp Range: -55 °C to +125 °C; Tolerance: 1%
R230 = RES: RES MF 2.05K  1/10W 1% AEC-Q200 0402; AGILE_PN: 470-30868; CAD_APPROVED: Yes; FPLIST: RC0402_25,RC0402_HD,0402_CC; HEIGHT: 0.40 MM; MFG_NAME01: KOA SPEER; MFG_PN01: RK73H1ETTP2051F; ROHS: Yes; Temp Range: -55C to +155C; Tolerance: 1%; VOLTAGE: 50V
R240 R250 = RES: RES MF 1.00 OHM 1/10W 1% 0603; AGILE_PN: 470-30469; CAD_APPROVED: Yes; FPLIST: RC0603_OV,RC0603,0603_CC; HEIGHT: 0.55 MM; MFG_NAME01: YAGEO AMERICA; MFG_PN01: RC0603FR-071RL; ROHS: Yes; Tolerance: 1%
R243 = RES: RES MF 10 OHM 1/16W 0.1% 0603; AGILE_PN: 470-82209; CAD_APPROVED: Yes; FPLIST: RC0603_OV,RC0603,0603_CC; HEIGHT: 0.55MM; MFG_NAME01: TE CONNECTIVITY LTD; MFG_PN01: CPF0603B10RE1; ROHS: Yes; Temp Range: -55C to +155C; Tolerance: 0.1%
R281 = RES: RES MF 2.2K 1/16W 5% 0402; AGILE_PN: 470-75636; CAD_APPROVED: Yes; FPLIST: RC0402_25,RC0402_HD,0402_CC; HEIGHT: 0.4 MM; MFG_NAME01: BOURNS; MFG_PN01: CR0402-JW-222GLF; ROHS: Yes; Tolerance: 5%
R441 = RES: RES MF 499 OHM 1/16W 1% 0402; AGILE_PN: 470-30807; CAD_APPROVED: Yes; FPLIST: RC0402_25,RC0402_HD,0402_CC; HEIGHT: 0.40 MM; MFG_NAME01: ROHM; MFG_PN01: MCR01MZPF4990; ROHS: Yes; Tolerance: 1%
TP29 TP32-TP34 TP37 TP38 TP52 TP53 TP56-TP58 TP63 TP68-TP70 TP80 TP81 TP91 TP92 TP106 TP108 TP109 TP116-TP121 TP124 TP126 TP127 TP130-TP132 TP139 TP145 = T_POINT_R: TEST POINT PAD .035 SMT, no part to order; AGILE_PN: 510-75618; ASSY_OPT: DNP; CAD_APPROVED: Yes; HEIGHT: 0.1MM; ROHS: Yes
U16 U17 U21 U64 = PAC1934_UQFN16_A: IC MULTI CHANNEL POWER/ENERGY MONITOR  2.7-5.5V UQFN16; 3D_Mechanical_Footprint_File: http://fcl.am.freescale.net/ALLEGRO/step/qfn16_0p65_4X4_a.step; AGILE_PN: 312-82072; CAD_APPROVED: Yes; HEIGHT: 0.55; MFG_NAME01: MICROCHIP TECHNOLOGY INC; ROHS: Yes; Temp Range: -40C to 85C; VOLTAGE: 2.7-5.5V
U18 = PCT2075__SON8_EP: IC I2C DIGITAL TEMP SENSOR AND THERMAL WDG 2.7-5.5V HWSON8; 3D_Mechanical_Footprint_File: http://fcl.am.freescale.net/ALLEGRO/step/hwson8_0p5_3p1x2p1.STEP; AGILE_PN: 312-81267; CAD_APPROVED: Yes; HEIGHT: 0.8; MFG_NAME01: NXP SEMICONDUCTORS; MFG_PN01: PCT2075TP,147; ROHS: Yes; VOLTAGE: 2.7-5.5V
U19 U24 = TPS22990NDMLT_WSON10_B: IC LOAD SWITCH 10A 2.5-5.5V WSON10; 3D_Mechanical_Footprint_File: http://fcl.am.freescale.net/ALLEGRO/step/wson10_0p5_2p1x3p1.STEP; AGILE_PN: 315-82218; CAD_APPROVED: Yes; HEIGHT: 0.8; MFG_NAME01: TEXAS INSTRUMENTS; MFG_PN01: TPS22990NDMLT; ROHS: Yes; Temp Range: -40°C ~ 105°C; VOLTAGE: 2.5-5.5V
U33 = RT9193-33PB: IC VREG LDO 3.3V 300MA SOT-23-5; AGILE_PN: 315-76265; CAD_APPROVED: Yes; HEIGHT: 1.295; MFG_NAME01: RICHTEK; ROHS: Yes
U42 = 93AA56BT_SOT23-6: IC MEM EEPROM SERIAL 2K 16BIT 2.5-5.5V SOT23-6; AGILE_PN: 334-77717; CAD_APPROVED: Yes; HEIGHT: 1.45; MFG_NAME01: MICROCHIP TECHNOLOGY INC; MFG_PN01: 93LC56BT-I/OT; ROHS: Yes; Temp Range: -40C to +85C; VOLTAGE: 2.5-5.5V
R27 R29 R30 R32 = RES: RES MF 4.7K 1/16W 5% 0402; AGILE_PN: 470-75626; CAD_APPROVED: Yes; FPLIST: RC0402_25,RC0402_HD,0402_CC,RC0402_X2; HEIGHT: 0.41mm; MFG_NAME01: NIC COMPONENTS CORP; MFG_PN01: NRCL04J472TRF; ROHS: Yes; Tolerance: 5%
R106-R109 = RES: RES MF 1.0K 1/16W 5% 0402; AGILE_PN: 470-75555; CAD_APPROVED: Yes; FPLIST: RC0402_25,RC0402_HD,RC0402_X2,0402_CC,CAPC0402_L; HEIGHT: 0.41mm; MFG_NAME01: VISHAY INTERTECHNOLOGY; MFG_PN01: CRCW04021K00JNED; RATING: 1/16W; ROHS: Yes; Tolerance: 5%
SW3 = CHS-04TA_SW: SW SPST SLD WSH 25MA 24V DIP-4 SMT; 3D_Mechanical_Footprint_File: ftp://fcl.am.freescale.net/ALLEGRO/step/sw_chs_04_a.step; AGILE_PN: 510-77691; CAD_APPROVED: Yes; HEIGHT: 2.5MM; MFG_NAME01: NIDEC COPAL ELECTRONICS CORP; ROHS: Yes

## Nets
GND: C36.2 C41.2 C42.2 C47.2 C48.2 C50.2 C52.2 C54.2 C58.2 C63.2 C64.2 C65.2 C66.2 C67.2 C71.2 C78.2 C96.2 C97.2 C124.2 C240.2 C243.2 C249.2 C272.2 C284.2 C311.2 R53.2 R54.2 R58.2 R59.2 R128.2 R150.2 R162.2 R176.2 R199.2 R229.2 R230.2 R421.2 R422.2 R423.2 R424.2 R441.2 R463.2 TP95.1(Pin1) U16.3(GND) U16.17(EP) U17.3(GND) U17.17(EP) U18.4(GND) U18.5(A2) U18.6(A1) U18.7(A0) U18.9(EP_GND) U19.6(GND) U21.3(GND) U21.17(EP) U24.6(GND) U33.2(GND) U42.2(VSS) U64.3(GND) U64.17(EP) Y1.2 Y1.4 ; also on sheet 7 8 9 10 11 12 13 17 18 19 20 21 22 23 24
VCC_FT_3V3: C50.1 C52.1 C54.1 C58.1 C64.1 C67.1 C71.1 C240.1 C272.1 C284.1 C311.1 D18.A R115.2 R120.2 R124.2 R145.2 R154.1 R180.2 R195.2 R296.1 R332.1 R333.1 R464.2 R470.2 U16.2(VDD) U16.15(VDD_I/O) U17.2(VDD) U17.15(VDD_I/O) U18.8(VCC) U21.2(VDD) U21.15(VDD_I/O) U42.6(VCC) U64.2(VDD) U64.15(VDD_I/O) ; also on sheet 7
VDD_1P8: R132.1 R182.1 R184.1 R200.1 R222.1 R234.1 R244.1 R261.1 TP81.1(TP) TP92.1(TP) TP109.1(TP) TP131.1(TP) ; also on sheet 19
VDD_1V8: R127.1 R261.2 TP132.1(TP) ; also on sheet 7 10 11 19 22 23 24
VDD_3P3: R126.1 R152.1 R161.1 R179.1 R185.1 R192.1 TP57.1(TP) TP69.1(TP) TP70.1(TP) ; also on sheet 19
VDD_3V3: R27.1 R29.1 R30.1 R32.1 R149.1 R179.2 TP56.1(TP) ; also on sheet 7 8 9 10 11 12 13 19 20 21 22 23 24
VDD_ANA_0P8: R251.1 R459.1 TP121.1(TP) ; also on sheet 19
VDD_ANA_0V8: R251.2 R450.1 TP126.1(TP) ; also on sheet 17
VDD_ANA_1V8: R183.1 R222.2 TP80.1(TP) ; also on sheet 17
VDD_SOC: R241.2 R461.1 R469.1 TP117.1(TP) ; also on sheet 17 19
VDD_SOC_0V85: R240.1 R460.1 TP116.1(TP) U24.3(VIN_1) U24.11(VIN_2) ; also on sheet 19
VDD_SOC_SW: R214.2 R215.2 TP85.1(Pin1) U24.5(ON)
VDD_USB_3V3: R165.1 R192.2 TP68.1(TP) ; also on sheet 17
ADC_IN0: U1.B8(ADC_IN0) ; also on sheet 23
ADC_IN1: U1.A8(ADC_IN1) ; also on sheet 23
CLKIN1: R54.1 TP20.1(Pin1) U1.A6(CLKIN1)
CLKIN2: R53.1 TP19.1(Pin1) U1.B6(CLKIN2)
CLKO01: R224.2 TP104.1(Pin1)
DCDC_5V: C124.1 R232.1 R260.1 TP139.1(TP) TP145.1(TP) U33.1(VIN) U33.3(EN) ; also on sheet 11 12 22
EE_CLK: R332.2 R342.1 TP158.1(Pin1) U42.4(CLK)
EE_CS: R333.2 R343.1 TP159.1(Pin1) U42.5(CS)
EE_DATA: R281.2 R295.1 TP147.1(Pin1) U42.3(DI)
EXP_nIRQ: R224.1 U1.T4(CCM_CLKO1) ; also on sheet 13
FSC_CTRL_H1: R215.1 ; also on sheet 7
FSC_CTRL_H2: R435.1 ; also on sheet 7
FT_EECLK: R342.2 ; also on sheet 7
FT_EECS: R343.2 ; also on sheet 7
FT_EEDATA: R295.2 ; also on sheet 7
FT_SCL: R155.1 R159.2 R164.2 R227.2 R451.2 TP37.1(TP) ; also on sheet 7
FT_SDA: R156.1 R160.2 R170.2 R228.2 R449.2 TP38.1(TP) ; also on sheet 7
FT_TEMP_nINT: R154.2 TP46.1(Pin1) U18.3(OS)
JTAG_TCK: R229.1 TP88.1(Pin1) U1.U3(DAP_TCLK_SWCLK) ; also on sheet 13
JTAG_TDI: TP96.1(Pin1) U1.P8(DAP_TDI) ; also on sheet 13
JTAG_TDO: TP86.1(Pin1) U1.T3(DAP_TDO_TRACESWO) ; also on sheet 13
JTAG_TMS: TP87.1(Pin1) U1.P6(DAP_TMS_SWDIO) ; also on sheet 13
LPD4_VDD1: R181.1 R234.2 TP91.1(TP) ; also on sheet 18
LPD4_VDD2: R148.1 R166.1 R174.2 TP53.1(TP) ; also on sheet 17 18
LPD4_VDD2_1V1: R167.1 R175.1 TP52.1(TP) U19.3(VIN_1) U19.11(VIN_2) ; also on sheet 19
LPD4_VDD2_SW: R435.2 R437.2 TP71.1(Pin1) U19.5(ON)
M1_SCL: R451.1 U64.4(SM_CLK)
M1_SDA: R449.1 U64.5(SM_DATA)
M2_SCL: R159.1 U16.4(SM_CLK)
M2_SDA: R160.1 U16.5(SM_DATA)
M3_SCL: R164.1 U17.4(SM_CLK)
M3_SDA: R170.1 U17.5(SM_DATA)
M4_SCL: R227.1 U21.4(SM_CLK)
M4_SDA: R228.1 U21.5(SM_DATA)
MX_POR_B: C36.1 R55.2 R56.2 TP21.1(Pin1) U1.B7(POR_B)
NVCC_1V8: R197.1 R244.2 TP108.1(TP) ; also on sheet 17
NVCC_3V3: R125.1 R185.2 TP58.1(TP) ; also on sheet 17
NVCC_BBSM_1P8: R243.1 R448.1 TP119.1(TP) ; also on sheet 19
NVCC_BBSM_1V8: R56.1 R57.1 R92.1 R243.2 R440.1 TP118.1(TP) ; also on sheet 17 23
NVCC_SD: R213.1 R250.1 TP120.1(TP) ; also on sheet 19
NVCC_SD2: R220.1 R250.2 TP127.1(TP) ; also on sheet 17 20 24
ONOFF: R92.2 TP27.1(Pin1) U1.D10(ONOFF) ; also on sheet 7 23
PMIC_ON_REQ: R57.2 R58.1 TP22.1(Pin1) U1.A7(PMIC_ON_REQ) ; also on sheet 7 12 19
PMIC_STBY_REQ: R59.1 TP23.1(Pin1) U1.C9(PMIC_STBY_REQ) ; also on sheet 7 19
POR_B: R55.1 ; also on sheet 7 19
RC_BT_MODE0: R109.1 R421.1 SW3.7 ; also on sheet 7
RC_BT_MODE1: R108.1 R422.1 SW3.5 ; also on sheet 7
RC_BT_MODE2: R107.1 R423.1 SW3.3 ; also on sheet 7
RC_BT_MODE3: R106.1 R424.1 SW3.1 ; also on sheet 7
S1_LPD4_VDD2: R134.1 R174.1 R175.2 TP63.1(TP) U19.10(VOUT)
S1_VDD_SOC_0V8: R240.2 R241.1 R466.1 TP106.1(TP) U24.10(VOUT)
SAI1_TXD0: R106.2 TP33.1(TP) ; also on sheet 13 20
SAI1_TXFS: R107.2 TP34.1(TP) ; also on sheet 13 20
SAI3_TX_SYNC: R108.2 TP32.1(TP) ; also on sheet 20 23
TAMPER0: U1.D6(TAMPER0) ; also on sheet 23
TAMPER1: U1.D8(TAMPER1) ; also on sheet 23
UART1_TXD: R109.2 TP29.1(TP) ; also on sheet 7 20
VLS_3V3: C65.1 C66.1 C243.1 C249.1 D18.C D19.C R214.1 R436.1 R437.1 R438.1 TP124.1(TP) U19.4(VBIAS) U24.4(VBIAS)
VSYS_5V: R231.1 R260.2 TP130.1(TP) ; also on sheet 19
XTALI_24M: C42.1 R105.1 TP31.1(Pin1) U1.A9(XTALI_24M) Y1.1
XTALI_32K: C48.1 QZ1.2 R104.1 TP30.1(Pin1) U1.A5(RTC_XTALI)
XTALO_24M: C41.1 R105.2 U1.B9(XTALO_24M) Y1.3
XTALO_32K: C47.1 QZ1.1 R104.2 U1.B5(RTC_XTALO)
N117383326: R281.1 R296.2 U42.1(DO)
N117385728: C274.1 R460.2 U64.11(SENSE1+)
N117385807: C274.2 R461.2 U64.12(SENSE1-)
N117385857: C283.1 R466.2 U64.13(SENSE2+)
N117385909: C283.2 R469.2 U64.14(SENSE2-)
N117385984: C265.1 R448.2 U64.8(SENSE3+)
N117385990: R441.1 U64.6(ADDRSEL)
N117386025: R463.1 R464.1 U64.1(SLOW/~{ALERT})
N117386063: C265.2 R440.2 U64.7(SENSE3-)
N117386111: R470.1 U64.16(~{PWRDN})
N117386128: C270.1 R459.2 U64.10(SENSE4+)
N117386168: C270.2 R450.2 U64.9(SENSE4-)
N117386249: C53.1 R132.2 U16.11(SENSE1+)
N117386325: C53.2 R127.2 U16.12(SENSE1-)
N117386356: C51.1 U16.13(SENSE2+)
N117386392: C51.2 U16.14(SENSE2-)
N117386460: C59.1 R167.2 U16.8(SENSE3+)
N117386466: R162.1 U16.6(ADDRSEL)
N117386498: R120.1 R128.1 U16.1(SLOW/~{ALERT})
N117386536: C59.2 R166.2 U16.7(SENSE3-)
N117386581: R115.1 U16.16(~{PWRDN})
N117386598: C56.1 R134.2 U16.10(SENSE4+)
N117386638: C56.2 R148.2 U16.9(SENSE4-)
N117386716: C57.1 R152.2 U17.11(SENSE1+)
N117386852: C57.2 R149.2 U17.12(SENSE1-)
N117386899: C55.1 R126.2 U17.13(SENSE2+)
N117386951: C55.2 R125.2 U17.14(SENSE2-)
N117387023: C62.1 R184.2 U17.8(SENSE3+)
N117387029: R176.1 U17.6(ADDRSEL)
N117387061: R145.1 R150.1 U17.1(SLOW/~{ALERT})
N117387099: C62.2 R183.2 U17.7(SENSE3-)
N117387144: R124.1 U17.16(~{PWRDN})
N117387161: C60.1 R161.2 U17.10(SENSE4+)
N117387201: C60.2 R165.2 U17.9(SENSE4-)
N117387282: C72.1 R200.2 U21.11(SENSE1+)
N117387358: C72.2 R197.2 U21.12(SENSE1-)
N117387408: C68.1 R182.2 U21.13(SENSE2+)
N117387460: C68.2 R181.2 U21.14(SENSE2-)
N117387535: C85.1 R232.2 U21.8(SENSE3+)
N117387541: R230.1 U21.6(ADDRSEL)
N117387573: R195.1 R199.1 U21.1(SLOW/~{ALERT})
N117387611: C85.2 R231.2 U21.7(SENSE3-)
N117387659: R180.1 U21.16(~{PWRDN})
N117387676: C79.1 R213.2 U21.10(SENSE4+)
N117387716: C79.2 R220.2 U21.9(SENSE4-)
N117391560: R436.2 U19.7(PG)
N117392496: C96.1 D19.A U33.5(VOUT)
N117392540: C97.1 U33.4(BP)
N117392714: R156.2 U18.1(SDA)
N117392721: R155.2 U18.2(SCL)
N117417066: C78.1 U24.1(CT)
N117417617: C63.1 U19.1(CT)
N117479041: R27.2 SW3.2
N117479043: R29.2 SW3.4
N117479045: R30.2 SW3.6
N117479047: R32.2 SW3.8
N118558640: R438.2 U24.7(PG)

Not connected (* = marked no-connect by the designer): U19 2(NC)*; U24 2(NC)*

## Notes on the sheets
sheet 1
- BOOT MODE CFG
- i.MX91 BOOT MODE
- BOOT_MODE[3:0]
  SW3[1:4]
- BOOT CORE
- BOOT DEVICE
- COMMENT
- 0000
  0001
  0010
  0011
  0100
  0101
  0110
  0111
- Cortex-A55
  Cortex-A55
  Cortex-A55
  Cortex-A55
  Cortex-A55
  Cortex-A55
  Cortex-A55
  Cortex-A55
- From internal fuses
  Serial Downloader
  USDHC1 8-bit eMMC 5.1
  USDHC2 4-bit SD3.0
  FlexSPI Serial NOR
  FlexSPI Serial NAND 2K page
  Reserved
  Reserved
- USB1
  with SFDP (JESD-216) discoverable parameters
- Boot Switch
- BMODE OVER DRV
- 1
- 2
- 3
- 4
- #BOOT_MODE3
- #BOOT_MODE1
- #BOOT_MODE2
- #BOOT_MODE0
- #SoC PU:
        22K-31K-54K <MIN-TYP-MAX> 1.8V
        27K-31K-43K <MIN-TYP-MAX> 3.3V
- #SoC PD:
        22K-31K-52K <MIN-TYP-MAX> 1.8V
        25K-31K-40K <MIN-TYP-MAX> 3.3V
sheet 2
- PAC1934T ADDR SEL RES
- Currt Sense Range SEL
- Curr Monitors
- Resistor (1%)
- SMBus Address
- 0 (TietoGND)
  499
  806
  1,270
  2,050
- 0010_000x
  0010_001x
  0010_010x
  0010_011x
  0010_100x
- VDD_SOC
- FT4232 I2C Address Table
- RS1-2
- RS1-1
- RS1-1+RS1-2
- Part
- Type
- Device
- Address
- U64
- M1
- PAC1934T
- 0x11(0010001x)
- U16
- M2
- PAC1934T
- 0x12(0010010x)
- 0.61V - 0.65V - 0.69V(Suspend)
  0.76V - 0.80V - 0.84V(Low drive)
  0.80V - 0.85V - 0.90V(Nominal)
- U17
- M3
- PAC1934T
- 0x13(0010011x)
- VIN: 0.6V - VBIAS
- RS1-1
- VBIAS: 2.5V - 5.5V
- 5A
- FSC
- 0.02 OHM
- RS
- U21
- M4
- PAC1934T
- 0x14(0010100x)
- 98mA
- 1+0.02 OHM
- FSC_CTRL=H, SW ON, large FSC,
  Default (w/ or w/o debug USB)
- U18
- T-sensor
- PCT2075
- 0x48(1001000x)
- RS5
- FSC_CTRL=L, SW OFF, small FSC
- Always-on LDO for Ld SW
- # VDD_SOC
- RS6
- LPD4_VDD2_1V1
- RS2-2
- RS2-1
- RS3
- 1.06V - 1.10V - 1.17V
- VIN: 0.6V - VBIAS
- VBIAS: 2.5V - 5.5V
- 2A
- FSC
- 0.05 OHM
- RS
- 48.8mA
- 2+0.05 OHM
- FSC_CTRL=H, SW ON, large FSC,
  Default (w/ or w/o debug USB)
- FSC_CTRL=L, SW OFF, small FSC
- SOM TEMP SENSOR
- RS2-1+RS2-2
- # LPD4_VDD2
- RS2-1
- OD
- #I2C ADDR: 0b'1001000x
- RS10
- Fixed Curr Sense RES
- RS12
- RS3
- SYS ID (RSV)
- RS4
- RS7
- RS5
- RS6
- RS7
- FSC: Vsense(100mV)/RS
- RS11
- RS8
- FSC
- RS
- 10mA
- 10 OHM
- RS9
- 20mA
- 4.99 OHM
- 100mA
- 1 OHM
- RS10
- 250mA
- 0.4 OHM
- RS11
- 1A
- 400mA
- 0.1 OHM
- 0.25 OHM
- 2A
- 0.05 OHM
- RS12
- 5A
- 0.02 OHM
- RS13
- RS8
- Power Measurement Equations:
- RS9
- I_sense = Vsense / Rs
  Vout     = Vsense- = V(sense+) - Vsense
  Power = I_sense x Vout
- RS4
- RS13
sheet 3
- i.MX91 MISC
- # System On/Off Button
- HI-Z
- HI-Z
- OH
- PD
- OL
- PU
- PU
- PD
- HI-Z
- PD
- OL
- RC filter to improve EMI performance.
- Close to signal.
- Caution:
- HI-Z
- HI-Z
- # At the first time of BBSM_1P8 ramping up,
  PMIC_ON_REQ / PMIC_STBY_REQ are HIGH-Z;
  About 1ms  delay,
    --PMIC_ON_REQ:strong output HIGH;
    --PMIC_STBY_REQ: strong output LOW.
- HI-Z
- HI-Z
- JTAG/SWD
sheet 4
- i.MX91 9x9 IOMUX:
- IOPAD
- Alt0
- Alt1
- Alt2
- Alt3
- Alt4
- Alt5
- Alt6
- Alt7
- Reset Status
- GPIO_IO00
  GPIO_IO01
  GPIO_IO02
  GPIO_IO03
  GPIO_IO04
  GPIO_IO05
  GPIO_IO06
  GPIO_IO07
  GPIO_IO08
  GPIO_IO09
  GPIO_IO10
  GPIO_IO11
  GPIO_IO12
  GPIO_IO13
  GPIO_IO14
  GPIO_IO15
  GPIO_IO16
  GPIO_IO17
  GPIO_IO18
  GPIO_IO19
  GPIO_IO20
  GPIO_IO21
  CCM_CLKO1
  DAP_TDI
  DAP_TMS_SWDIO
  DAP_TCLK_SWCLK
  DAP_TDO_TRACESWO
  ENET1_MDC
  ENET1_MDIO
  ENET1_TD3
  ENET1_TD2
  ENET1_TD1
  ENET1_TD0
  ENET1_TX_CTL
  ENET1_TXC
  ENET1_RX_CTL
  ENET1_RXC
  ENET1_RD0
  ENET1_RD1
  ENET1_RD2
  ENET1_RD3
  SD1_CLK
  SD1_CMD
  SD1_DATA0
  SD1_DATA1
  SD1_DATA2
  SD1_DATA3
  SD1_DATA4
  SD1_DATA5
  SD1_DATA6
  SD1_DATA7
  SD1_STROBE
  SD2_VSELECT
  SD3_CLK
  SD3_CMD
  SD3_DATA0
  SD3_DATA1
  SD3_DATA2
  SD3_DATA3
  SD2_CD_B
  SD2_CLK
  SD2_CMD
  SD2_DATA0
  SD2_DATA1
  SD2_DATA2
  SD2_DATA3
  SD2_RESET_B
  I2C1_SCL
  I2C1_SDA
  I2C2_SCL
  I2C2_SDA
  UART1_RXD
  UART1_TXD
  UART2_RXD
  UART2_TXD
  PDM_CLK
  PDM_BIT_STREAM0
  PDM_BIT_STREAM1
  SAI1_TXFS
  SAI1_TXC
  SAI1_TXD0
  SAI1_RXD0
  WDOG_ANY
- gpio2.IO[0]
  gpio2.IO[1]
  gpio2.IO[2]
  gpio2.IO[3]
  gpio2.IO[4]
  gpio2.IO[5]
  gpio2.IO[6]
  gpio2.IO[7]
  gpio2.IO[8]
  gpio2.IO[9]
  gpio2.IO[10]
  gpio2.IO[11]
  gpio2.IO[12]
  gpio2.IO[13]
  gpio2.IO[14]
  gpio2.IO[15]
  gpio2.IO[16]
  gpio2.IO[17]
  gpio2.IO[18]
  gpio2.IO[19]
  gpio2.IO[20]
  gpio2.IO[21]
  ccmsrcgpcmix.CLKO1
  dap.TDI
  dap.TMS_SWDIO
  dap.TCLK_SWCLK
  dap.TDO_TRACESWO
  enet_qos.MDC
  enet_qos.MDIO
  enet_qos.RGMII_TD3
  enet_qos.RGMII_TD2
  enet_qos.RGMII_TD1
  enet_qos.RGMII_TD0
  enet_qos.RGMII_TX_CTL
  enet_qos.RGMII_TXC
  enet_qos.RGMII_RX_CTL
  enet_qos.RGMII_RXC
  enet_qos.RGMII_RD0
  enet_qos.RGMII_RD1
  enet_qos.RGMII_RD2
  enet_qos.RGMII_RD3
  usdhc1.CLK
  usdhc1.CMD
  usdhc1.DATA0
  usdhc1.DATA1
  usdhc1.DATA2
  usdhc1.DATA3
  usdhc1.DATA4
  usdhc1.DATA5
  usdhc1.DATA6
  usdhc1.DATA7
  usdhc1.STROBE
  usdhc2.VSELECT
  usdhc3.CLK
  usdhc3.CMD
  usdhc3.DATA0
  usdhc3.DATA1
  usdhc3.DATA2
  usdhc3.DATA3
  usdhc2.CD_B
  usdhc2.CLK
  usdhc2.CMD
  usdhc2.DATA0
  usdhc2.DATA1
  usdhc2.DATA2
  usdhc2.DATA3
  usdhc2.RESET_B
  i2c1.SCL
  i2c1.SDA
  i2c2.SCL
  i2c2.SDA
  uart1.RX
  uart1.TX
  uart2.RX
  uart2.TX
  pdm.CLK
  pdm.BIT_STREAM[0]
  pdm.BIT_STREAM[1]
  sai1.TX_SYNC
  sai1.TX_BCLK
  sai1.TX_DATA[0]
  sai1.RX_DATA[0]
  wdog1.WDOG_ANY
- i2c3.SDA
  i2c3.SCL
  i2c4.SDA
  i2c4.SCL
  tpm3.CH0
  tpm4.CH0
  tpm5.CH0
  spi3.PCS1
  spi3.PCS0
  spi3.SIN
  spi3.SOUT
  spi3.SCK
  tpm3.CH2
  tpm4.CH2
  uart3.TX
  uart3.RX
  sai3.TX_BCLK
  sai3.MCLK
  sai3.RX_BCLK
  sai3.RX_SYNC
  sai3.RX_DATA[0]
  sai3.TX_DATA[0]
  mqs2.LEFT
  mqs2.RIGHT
  uart3.DCD_B
  uart3.RIN_B
  enet2.TX_CLK/ENET_CLK_ROOT
  uart3.RTS_B
  uart3.TX
  uart3.DTR_B
  enet_qos.TX_ER
  uart3.DSR_B
  enet_qos.RX_ER
  uart3.RX
  uart3.CTS_B
  flexspi.A_SS1_B
  flexspi.A_DATA[4]
  flexspi.A_DATA[5]
  flexspi.A_DATA[6]
  flexspi.A_DATA[7]
  flexspi.A_DQS
  usdhc2.WP
  flexspi.A_SCLK
  flexspi.A_SS0_B
  flexspi.A_DATA[0]
  flexspi.A_DATA[1]
  flexspi.A_DATA[2]
  flexspi.A_DATA[3]
  enet_qos.1588_EVENT0_IN
  enet_qos.1588_EVENT0_OUT
  enet2.1588_EVENT0_IN
  enet2.1588_EVENT0_OUT
  enet2.1588_EVENT1_IN
  enet2.1588_EVENT1_OUT
  lptmr2.ALT1
  lptmr2.ALT2
  i3c1.SCL
  i3c1.SDA
  i3c1.PUR
  seco.RX
  seco.TX
  uart1.CTS_B
  uart1.RTS_B
  mqs1.LEFT
  mqs1.RIGHT
  sai1.TX_DATA[1]
  uart2.CTS_B
  uart2.RTS_B
  sai1.MCLK
- isi.PCLK
  isi.D[0]
  isi.FRAME_VALID
  isi.LINE_VALID
  pdm.CLK
  pdm.BIT_STREAM[0]
  pdm.BIT_STREAM[1]
  isi.D[1]
  isi.D[2]
  isi.D[3]
  isi.D[4]
  isi.D[5]
  pdm.BIT_STREAM[2]
  pdm.BIT_STREAM[3]
  isi.D[6]
  isi.D[7]
  pdm.BIT_STREAM[2]
  isi.D[8]
  isi.D[9]
  pdm.BIT_STREAM[3]
  pdm.BIT_STREAM[0]
  pdm.CLK
  i3c2.SCL
  i3c2.SDA
  can2.TX
  can2.RX
  i3c2.PUR
  spi2.SCK
  spi2.SIN
  spi2.PCS0
  spi2.SOUT
  usdhc1.RESET_B
  usdhc1.CD_B
  usdhc1.WP
  lptmr2.ALT3
  uart1.CTS_B
  uart1.RTS_B
  uart2.CTS_B
  uart2.RTS_B
  i2c4.SDA
  i2c4.SCL
  i3c2.SCL
  i3c2.SDA
  i3c2.PUR
  can2.TX
  can2.RX
  mqs2.RIGHT
  mqs2.LEFT
  uart1.DCD_B
  uart1.RIN_B
  uart2.DCD_B
  uart2.RIN_B
  spi2.SIN
  spi2.PCS0
  spi2.SOUT
  spi2.SCK
  spi1.PCS1
  spi2.PCS1
  spi1.PCS0
  spi1.SIN
  spi1.SCK
  spi1.SOUT
- lcdif.PCLK
  lcdif.DE
  lcdif.VSYNC
  lcdif.HSYNC
  lcdif.D[0]
  lcdif.D[1]
  lcdif.D[2]
  lcdif.D[3]
  lcdif.D[4]
  lcdif.D[5]
  lcdif.D[6]
  lcdif.D[7]
  lcdif.D[8]
  lcdif.D[9]
  lcdif.D[10]
  lcdif.D[11]
  lcdif.D[12]
  lcdif.D[13]
  lcdif.D[14]
  lcdif.D[15]
  lcdif.D[16]
  lcdif.D[17]
  can2.TX
  can2.RX
  usb1.OTG_ID
  usb1.OTG_PWR
  usb2.OTG_ID
  usb2.OTG_OC
  usb1.OTG_OC
  usb2.OTG_PWR
  lptmr2.ALT1
  lptmr2.ALT2
  lptmr2.ALT3
  spi2.SCK
  spi2.SIN
  spi2.PCS0
  spi2.SOUT
  spi2.PCS1
  spi1.PCS1
  spi1.PCS0
  spi1.SIN
  spi1.SCK
  spi1.SOUT
  i2c1.SCL
  i2c1.SDA
  i3c2.PUR_B
  uart1.TX
  uart1.RX
  uart2.TX
  uart2.RX
  tpm2.CH0
  tpm2.CH1
  tpm2.CH2
  tpm2.CH3
  tpm1.CH0
  tpm1.CH1
  tpm1.CH2
  tpm1.CH3
  tpm1.EXTCLK
  tpm2.EXTCLK
  uart2.DTR_B
  uart1.DSR_B
  uart1.DTR_B
  uart2.DSR_B
- spi6.PCS0
  spi6.SIN
  spi6.SOUT
  spi6.SCK
  spi7.PCS0
  spi7.SIN
  spi7.SOUT
  spi7.SCK
  tpm6.CH0
  tpm3.EXTCLK
  tpm4.EXTCLK
  tpm5.EXTCLK
  spi8.PCS0
  spi8.SIN
  spi8.SOUT
  spi8.SCK
  uart3.CTS_B
  uart3.RTS_B
  spi5.PCS0
  spi5.SIN
  spi5.SOUT
  spi5.SCK
  sai1.RX_SYNC
  sai1.RX_BCLK
  sai1.MCLK
  lptmr1.ALT1
  lptmr1.ALT2
  lptmr1.ALT3
  mqs1.LEFT
  can1.RX
  can1.TX
  mqs1.RIGHT
- uart5.TX
  uart5.RX
  uart5.CTS_B
  uart5.RTS_B
  uart6.TX
  uart6.RX
  uart6.CTS_B
  uart6.RTS_B
  uart7.TX
  uart7.RX
  uart7.CTS_B
  uart7.RTS_B
  uart8.TX
  uart8.RX
  uart8.CTS_B
  uart8.RTS_B
  spi4.PCS2
  spi4.PCS1
  spi4.PCS0
  spi4.SIN
  spi4.SOUT
  spi4.SCK
  gpio3.IO[26]
  gpio3.IO[28]
  gpio3.IO[29]
  gpio3.IO[30]
  gpio3.IO[31]
  gpio4.IO[0]
  gpio4.IO[1]
  gpio4.IO[2]
  gpio4.IO[3]
  gpio4.IO[4]
  gpio4.IO[5]
  gpio4.IO[6]
  gpio4.IO[7]
  gpio4.IO[8]
  gpio4.IO[9]
  gpio4.IO[10]
  gpio4.IO[11]
  gpio4.IO[12]
  gpio4.IO[13]
  gpio3.IO[8]
  gpio3.IO[9]
  gpio3.IO[10]
  gpio3.IO[11]
  gpio3.IO[12]
  gpio3.IO[13]
  gpio3.IO[14]
  gpio3.IO[15]
  gpio3.IO[16]
  gpio3.IO[17]
  gpio3.IO[18]
  gpio3.IO[19]
  gpio3.IO[20]
  gpio3.IO[21]
  gpio3.IO[22]
  gpio3.IO[23]
  gpio3.IO[24]
  gpio3.IO[25]
  gpio3.IO[0]
  gpio3.IO[1]
  gpio3.IO[2]
  gpio3.IO[3]
  gpio3.IO[4]
  gpio3.IO[5]
  gpio3.IO[6]
  gpio3.IO[7]
  gpio1.IO[0]
  gpio1.IO[1]
  gpio1.IO[2]
  gpio1.IO[3]
  gpio1.IO[4]
  gpio1.IO[5]/ccmsrcgpcmix.BOOT_MODE[0]
  gpio1.IO[6]
  gpio1.IO[7]/ccmsrcgpcmix.BOOT_MODE[1]
  gpio1.IO[8]
  gpio1.IO[9]
  gpio1.IO[10]
  gpio1.IO[11]/ccmsrcgpcmix.BOOT_MODE[2]
  gpio1.IO[12]
  gpio1.IO[13]/ccmsrcgpcmix.BOOT_MODE[3]
  gpio1.IO[14]
  gpio1.IO[15]
- i2c5.SDA
  i2c5.SCL
  i2c6.SDA
  i2c6.SCL
  i2c6.SDA
  i2c6.SCL
  i2c7.SDA
  i2c7.SCL
  i2c7.SDA
  i2c7.SCL
  i2c8.SDA
  i2c8.SCL
  i2c8.SDA
  i2c8.SCL
  uart4.TX
  uart4.RX
  uart4.CTS_B
  uart4.RTS_B
  tpm5.CH2
  tpm6.CH2
  tpm3.CH1
  tpm4.CH1
  uart5.RX
  uart5.RTS_B
  uart5.CTS_B
  uart5.TX
  i2c1.SCL
  i2c1.SDA
  i2c2.SCL
  i2c2.SDA
  i3c2.PUR_B
  i3c1.PUR_B
  can1.TX
  can1.RX
  sai1.MCLK
- sai3.RX_SYNC
  sai3.TX_DATA[0]
  sai3.RX_BCLK
  sai3.TX_SYNC
  sai3.TX_SYNC
- input w/ PD
  input w/ PD
  input w/ PD
  input w/ PD
  input w/ PD
  input w/ PD
  input w/ PD
  input w/ PD
  input w/ PD
  input w/ PD
  input w/ PD
  input w/ PD
  input w/ PD
  input w/ PD
  input w/ PD
  input w/ PD
  input w/ PD
  input w/ PD
  input w/ PD
  input w/ PD
  input w/ PD
  input w/ PD
  output low
  input w/ PU
  input w/ PU
  input w/ PD
  input wo/ PD/PU
  input w/ PD
  input w/ PD
  input w/ PD
  input w/ PD
  input w/ PD
  input w/ PD
  input w/ PD
  input w/ PD
  input w/ PD
  input w/ PD
  input w/ PD
  input w/ PD
  input w/ PD
  input w/ PD
  input w/ PD
  input w/ PD
  input w/ PD
  input w/ PD
  input w/ PD
  input w/ PD
  input w/ PD
  input w/ PD
  input w/ PD
  input w/ PD
  input w/o PU/PD
  input w/ PD
  input w/ PD
  input w/ PD
  input w/ PD
  input w/ PD
  input w/ PD
  input w/ PD
  input w/ PD
  input w/ PD
  input w/ PD
  input w/ PD
  input w/ PD
  input w/ PD
  input w/ PD
  input w/ PD
  input w/ PD
  input w/ PD
  input w/ PD
  input w/ PD
  input w/ PD
  input w/ PD
  input w/ PD
  input w/ PD
  input w/ PD
  input w/ PD
  input w/ PD
  input w/ PD
  input w/ PD
  input w/ PD
  input w/ PD
  input w/ PU
sheet 5
- NOTE:
- i.MX91 I2C DEV TABLE
- PART
- DEVICE
- I2C ADDR
- PORT
- Max SPEED
- VOL
- DESCRIPTION
- U15
- PCAL6524HEAZ
- 0x22 (0b'0100010x)
- MX-I2C2
- 1MHz Fm+
- 3.3V
- IO EXP for IRQ/OUTPUT
- U23
- MPF9453AVMA1HN
- 0x32 (0b'0110010x)
- MX-I2C2
- 1MHz Fm+
- 3.3V
- PMIC
- U49
- PTN5110NHQZ
- 0x52 (0b'1010010x)
- MX-I2C1
- 400KHz
- 3.3V
- USB C PD
- U48
- PTN5110NHQZ
- 0x50 (0b'1010000x)
- MX-I2C1
- 400KHz
- 3.3V
- USB C  USB1
- U47
- NX20P3483UK
- 0x71 (0b'1110010x)
- MX-I2C1
- 400KHz
- 3.3V
- USB Load Switch
- J8
- PCAL6408AEX1Z
- 0x20 (0b'0100000x)
- MX-I2C1
- 400KHz
- 1.8V
- M.2 / NGFF KEY-E
- U11
- P3T1085UK
- 0x48 (0b'1001000x)
- MX-I2C1/I3C1
- I3C-12.5MHz
- 3.3V
- Temp Sensor (I3C support)
- U12
- PCF2131TF
- 0x53 (0b'1010011x)
- MX-I2C1
- 400KHz
- 3.3V
- Ext RTC
- FT4232 I2C DEV TABLE
- PART
- DEVICE
- I2C ADDR
- PORT
- Max SPEED
- VOL
- DESCRIPTION
- U13
- PCA9655EMTTXG
- 0x21 (0b'0100001x)
- FTDI-I2C
- 1MHz Fm+
- 3.3V
- IO EXP
- U64
- PAC1934T
- 0x11 (0b'0010001x)
- FTDI-I2C
- 1MHz Fm+
- 3.3V
- Power Monitor
- U16
- PAC1934T
- 0x12 (0b'0010010x)
- FTDI-I2C
- 1MHz Fm+
- 3.3V
- Power Monitor
- U17
- PAC1934T
- 0x13 (0b'0010011x)
- FTDI-I2C
- 1MHz Fm+
- 3.3V
- Power Monitor
- U21
- PAC1934T
- 0x14 (0b'0010100x)
- FTDI-I2C
- 1MHz Fm+
- 3.3V
- Power Monitor
- U18
- PCT2075
- 0x48 (0b'1001000x)
- FTDI-I2C
- 1MHz Fm+
- 3.3V
- Temp Sensor
sheet 6
- IMX91LP4QSB-09 Power Measurement Diagram
- VBUS_USB_DBG
- FT_3V3
- PMIC
- i.MX91 9x9
- NXP PF9453
- VDD
- VDDIO
- NVCC_BBSM_1P8
- RS5
- NVCC_BBSM_1V8
- LDO_SNVS
  (1.8V 10mA)
- NVCC_BBSM_1P8
- CH1
- Monitor 1
- VDD_SOC
- I2C
- CH2
- PAC1934
- 499ohm
- NVCC_BBSM_1V8
- CH3
- ADDRSEL
- 0x11(0010001x)
- BUCK2
  (0.65/0.8/0.85V 2700mA)
- VDD_SOC_0V85
- RS1
- VDD_SOC
- VDD_ANA_0V8
- CH4
- VDD_SOC
- CSRS 1
- VDD_ANA0_0P8
- VBUS_USB_DBG
- FT_3V3
- VDD_ANA_0P8
- RS6
- VDD_ANA_0V8
- LDO2
  (0.8V 200mA)
- VDD_ANA1_0P8
- VDD_USB_0P8
- VDD
- VDDIO
- DCDC_5V
- RS4
- VSYS_5V
- DCDC
- VDD_1V8
- CH1
- Monitor 2
- VDD_1P8
- RS7
- VDD_ANA_1V8
- VDD_ANA0_1P8
  VDD_ANA1_1P8
  VDD_USB_1P8
- I2C
- BUCK3
  (1.8V  2000mA)
- CH2
- PAC1934
- 806ohm
- CH3
- ADDRSEL
- NVCC_1V8
- LPD4_VDD2
- RS8
- 0x12(0010010x)
- NVCC_xxx_1P8
- CH4
- VDD_3P3
- RS12
- NVCC_3V3
- BUCK4
  (3.3V 2500mA)
- NVCC_xxx_3P3
- VBUS_USB_DBG
- FT_3V3
- RS11
- VDD_USB_3V3
- VDD_USB_3P3
- NVCC_SD
- RS13
- NVCC_SD2
- VDD
- VDDIO
- LDO1
  (3.3/1.8V  250mA)
- Monitor 3
- NVCC_SD2
- VDD_3V3
- CH1
- I2C
- PAC1934
- NVCC_3V3
- CH2
- 1270ohm
- LPD4_VDD2_1V1
- RS2
- LPD4_VDD2
- VDD_ANA_1V8
- CH3
- ADDRSEL
- BUCK1
  (1.1V 2000mA)
- VDD2_DDR
- 0x13(0010011x)
- VDD_USB_3V3
- CH4
- CSRS 2
- VBUS_USB_DBG
- FT_3V3
- LPD4_VDD1
- LPDDR4
- RS9
- VDD1
- VDD
- VDDIO
- Monitor 4
- M1
- VDD2/VDDQ
- NVCC_1V8
- CH1
- I2C
- PAC1934
- LPD4_VDD1
- CH2
- 2050ohm
- M2
- VSYS_5V
- CH3
- ADDRSEL
- VDD_1V8
- M3
- RS3
- Peripherals
- 0x14(0010100x)
- VDD_1V8
- NVCC_SD2
- CH4
- RS10
- VDD_3V3
- M4
- VDD_3V3
- Remote Debug
- Current Sense Range Select Circuit
- IO Expansion
- VLS_3V3
- FT_3V3
- PCA9655E
- Current sense range
  select circuit (CSRS)
- 0x21 (0100001x)
- Load SW
- USB to
  UART/I2C/JTAG
- Always-on power
- FSC Ctrl
- Isolation
    Buffer
- I2C
- FSC(full scale current) Ctrl
- VLS_3V3
- VCC
- EN
- Default high for enable
- FT4232H
- Vin
- Vout
- Large resistor
   for small FSC
- Small resistor
   for large FSC
- USB Type-C
  Debug Port
- Positive
  sample point 1
- Positive
  sample point 2
- Negative
  sample point
- The first positive sample point is used for small FSC, and second positive sample point is used for large FSC.
